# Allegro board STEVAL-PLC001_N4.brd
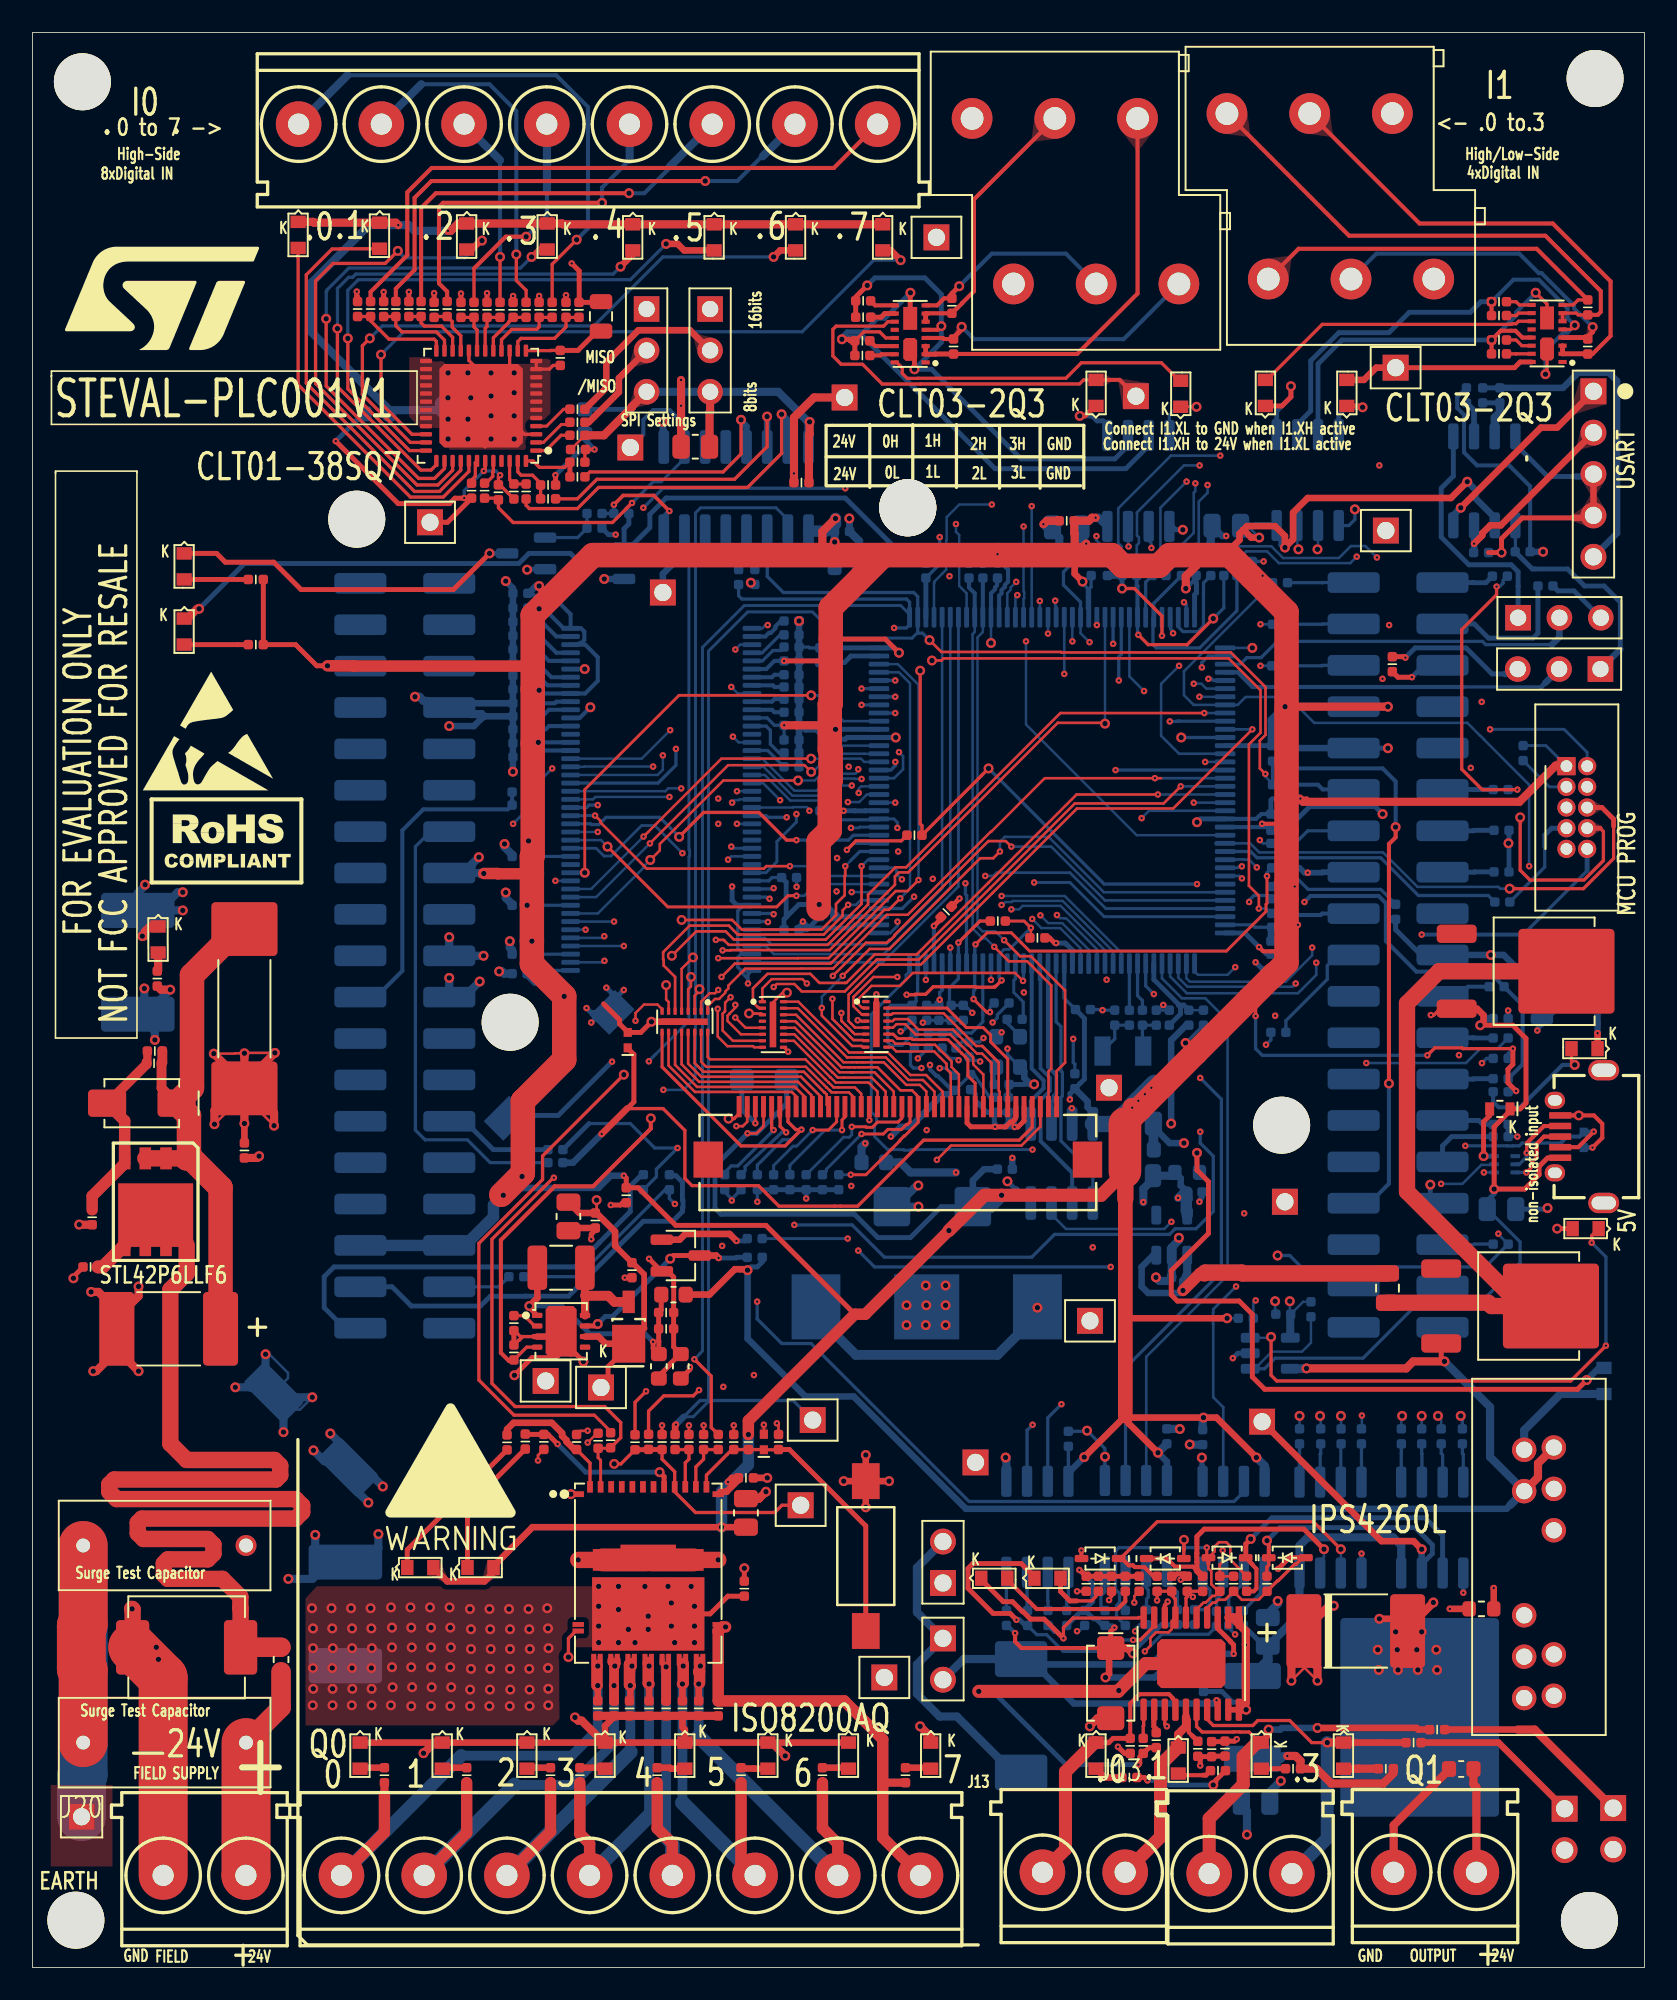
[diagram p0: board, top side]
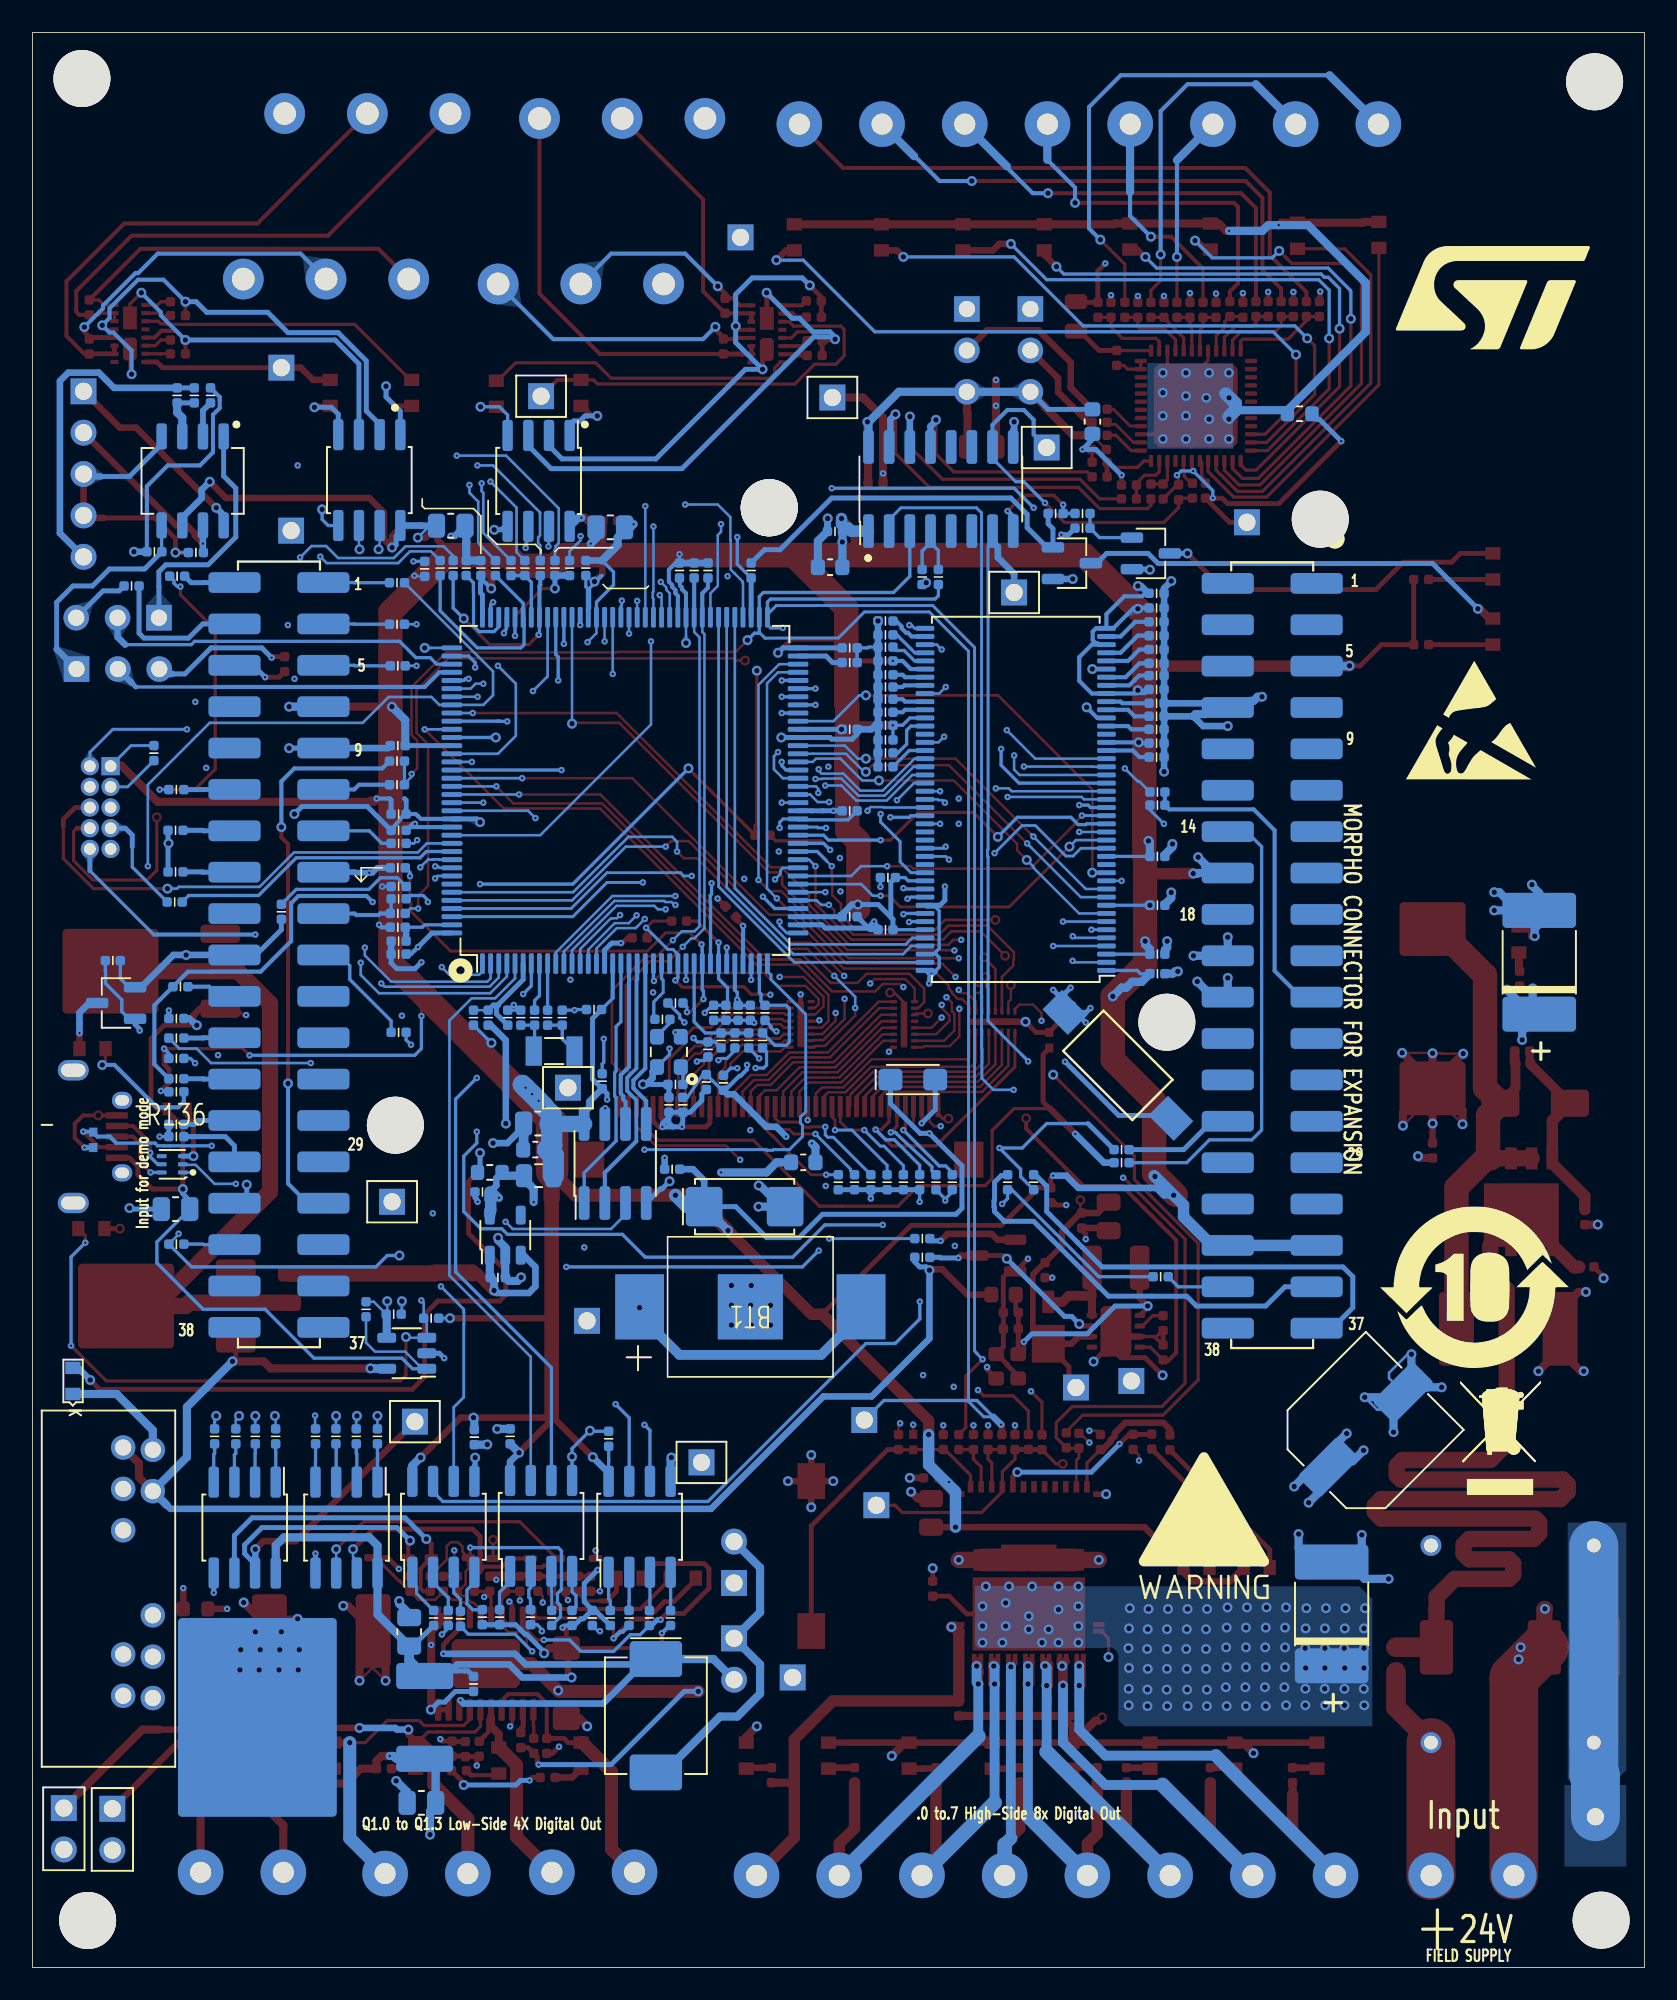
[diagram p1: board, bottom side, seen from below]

Outline 98.99 x 118.77 mm; copper layers: TOP, POWER PLANE, LOGIC_PLANE, BOTTOM. Coordinates in mm from the lower left corner of the outline.
Outline path: 0,118.77 0,0 98.99,0 98.99,118.77 0,118.77

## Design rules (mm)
constraint set DEFAULT: min track width 0.152, pair gap 0.15
net group FMC_ADD[0..13]: nets FMC_ADD.A0 FMC_ADD.A1 FMC_ADD.A2 FMC_ADD.A3 FMC_ADD.A4 FMC_ADD.A5 FMC_ADD.A6 FMC_ADD.A7 FMC_ADD.A8 FMC_ADD.A9 FMC_ADD.A10 FMC_ADD.A11 FMC_ADD.BA_0 FMC_ADD.BA_1
net group FMC_CTRL[0..7]: nets FMC_CTRL.NBL0 FMC_CTRL.NBL1 FMC_CTRL.SDCKE0 FMC_CTRL.SDCLK FMC_CTRL.SDNCAS FMC_CTRL.SDNE0 FMC_CTRL.SDNRAS FMC_CTRL.SDNWE
net group FMC_DATA[0..15]: nets FMC_DATA.D0 FMC_DATA.D1 FMC_DATA.D2 FMC_DATA.D3 FMC_DATA.D4 FMC_DATA.D5 FMC_DATA.D6 FMC_DATA.D7 FMC_DATA.D8 FMC_DATA.D9 FMC_DATA.D10 FMC_DATA.D11 FMC_DATA.D12 FMC_DATA.D13 FMC_DATA.D14 FMC_DATA.D15
net group LCD_BLUE[0..5]: nets LCD_BLUE.B2 LCD_BLUE.B3 LCD_BLUE.B4 LCD_BLUE.B5 LCD_BLUE.B6 LCD_BLUE.B7
net group LCD_GREEN[0..5]: nets LCD_GREEN.G2 LCD_GREEN.G3 LCD_GREEN.G4 LCD_GREEN.G5 LCD_GREEN.G6 LCD_GREEN.G7
net group LCD_RED[0..5]: nets LCD_RED.R2 LCD_RED.R3 LCD_RED.R4 LCD_RED.R5 LCD_RED.R6 LCD_RED.R7
net group USB[0..5]: nets USB.OTG_FS_DM USB.OTG_FS_DP USB.OTG_FS_ID USB.OTG_FS_VBUS USB.OVER_CURRENT USB.POWER_SWITCH_ON

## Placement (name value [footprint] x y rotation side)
BT1  3030TR  [CELL_HOLDER_KEYSTONE-3030TR]  54.91 40.55 0 bottom
C1  33pF  [C_0402]  28.61 90.55 90 top
C2  33pF  [C_0402]  29.56 90.6 270 top
C3  33pF  [C_0402]  31.66 91 0 top
C4  33pF  [C_0402]  33.46 92.4 0 top
C5  4.7uF  [C_0805]  40.7 93.35 180 top
C6  100nF  [C_0402]  33.5 93.18 180 top
C7  22nF  [C_0402]  31.11 101.75 270 top
C8  22nF  [C_0402]  29.51 101.75 270 top
C9  22nF  [C_0402]  27.91 101.75 270 top
C10  22nF  [C_0402]  26.31 101.75 270 top
C11  33nF  [C_0402]  32.41 98.8 270 top
C12  22nF  [C_0402]  24.66 101.75 270 top
C13  22nF  [C_0402]  23.11 101.8 270 top
C14  100nF  [C_0402]  47.22 91.15 180 top
C15  10uF  [C_0603]  50.01 85.95 0 bottom
C16  100nF  [C_0402]  49.71 88.15 0 bottom
C17  22nF  [C_0402]  21.56 101.8 270 top
C18  22nF  [C_0402]  19.96 101.8 270 top
C19  10nF  [C_0402]  51.01 101.3 180 top
C20  10nF  [C_0402]  56.46 102 90 top
C21  10nF  [C_0402]  50.96 98.95 180 top
C22  4.7uF  [C_0805]  63.51 88.4 180 bottom
C23  10nF  [C_0402]  56.56 99.5 90 top
C24  100nF  [C_0402]  63.51 88.8 0 top
C25  10nF  [C_0402]  90.06 101.4 180 top
C26  10nF  [C_0402]  95.51 101.9 90 top
C27  10nF  [C_0402]  90.06 99.05 180 top
C28  10nF  [C_0402]  95.51 99.5 90 top
C29  100nF  [C_0402]  74.91 85.85 270 bottom
C30  4.7uF  [C_0805]  73.31 88.5 180 bottom
C31  100nF  [C_0402]  66.26 23.55 90 top
C32  1pF  [C_0402]  72.91 23.55 270 top
C33  1pF  [C_0402]  73.76 23.55 270 top
C34  1uF  [C_0402]  72.41 13.4 90 top
C35  100nF  [C_0402]  67.96 23.55 90 top
C36  100n  [C_0402]  73.23 13.43 90 top
C37  4.7uF/63V  [TAN_2917]  81.26 20.65 0 top
C38  1pF  [C_0402]  70.91 23.55 270 top
C39  1pF  [C_0402]  69.96 23.55 270 top
C40  1uF  [C_0402]  64.71 23.55 270 top
C41  100nF  [C_0402]  71.86 32.55 270 bottom
C42  100nF  [C_0402]  69.66 32.6 90 bottom
C43  1uF  [C_0402]  64.61 21.45 270 bottom
C44  100nF  [C_0402]  63.61 32.45 90 bottom
C45  4.7uF/63V  [TAN_2917]  19.21 21.7 90 bottom
C46  10pF  [C_0402]  43.71 23.25 270 top
C47  22nF  [C_0402]  42.11 15.9 90 top
C48  22nF  [C_0402]  40.91 15.9 90 top
C49  22nF  [C_0402]  39.91 15.9 90 top
C50  10pF  [C_0402]  43.06 32.25 270 top
C51  22nF  [C_0402]  38.91 15.9 90 top
C52  22nF  [C_0402]  37.86 15.9 90 top
C53  33pF  [C_0402]  34.73 32.33 270 top
C54  33pF  [C_0402]  38.66 32.25 270 top
C55  33pF  [C_0402]  41.21 32.25 270 top
C56  22nF  [C_0402]  36.66 15.9 90 top
C57  33pF  [C_0402]  40.31 32.25 270 top
C58  22nF  [C_0402]  35.71 15.9 90 top
C59  22nF  [C_0402]  34.71 15.9 90 top
C60  4.7uF  [C_0805]  43.81 27.9 90 top
C61  100nF  [C_0402]  43.81 30.05 0 top
C62  10nF  [C_0402]  38.91 40.2 180 top
C63  4.7uF  [C_0805]  32.91 46.1 270 top
C64  10nF  [C_0402]  38.91 39.2 180.1 top
C65  4.7uF  [C_0603]  38.46 36.9 270 top
C66  10nF  [C_0402]  36.81 42.8 90 top
C67  100nF  [C_0402]  36.46 47.4 90 top
C68  4.7uF  [CAPPM320X160X120L75X120N]  44.93 54.5 180 bottom
C69  100nF  [C_0402]  29.91 61 180 bottom
C70  100nF  [C_0402]  29.91 62.2 180 bottom
C71  100nF  [C_0402]  46.61 63.7 0 bottom
C72  100nF  [C_0402]  29.91 65.2 180 bottom
C73  100nF  [C_0402]  46.46 66.9 0 bottom
C74  100nF  [C_0402]  29.91 68.2 180 bottom
C75  100nF  [C_0402]  29.96 75.15 180 bottom
C76  100nF  [C_0402]  46.61 75.35 0 bottom
C77  100nF  [C_0402]  46.61 76.25 0 bottom
C78  100nF  [C_0402]  29.96 78.45 180 bottom
C79  100nF  [C_0402]  46.61 80.2 0 bottom
C80  100nF  [C_0402]  29.96 84.35 180 bottom
C81  100nF  [C_0402]  29.96 83.45 180 bottom
C82  100nF  [C_0402]  64.01 54.4 270 bottom
C83  4.7uF  [C_0805]  67.96 51.8 0 bottom
C84  4n7/3kV  [CAPRB1000W60L1300T550H2000]  8.11 13.8 180 top
C85  4.7uF  [TAN_2917]  6.46 61.7 90 bottom
C86  2.2uF  [C_0402]  3.56 43 180 top
C87  4.7uF/63V  [TAN_2917]  8.36 39.2 180 top
C88  100uF  [CAPAE830X1000D890L290X95N]  17.11 33 135 bottom
C89  100nF  [C_0402]  13.01 50.15 270 top
C90  NM  [C_0402]  7.46 55.5 180 top
C91  4n7/3kV  [CAPRB1000W60L1300T550H2000]  8.11 25.9 0 top
C92  4.7uF  [C_0805]  90.21 46.55 0 bottom
C93  0.33  [C_0805]  75.11 10.1 0 bottom
C94  10nF  [C_0402]  71.91 17.4 90 bottom
C95  10uF  [C_0805]  75.86 20.6 90 bottom
C96  1uF  [C_0402]  71.36 47.6 0 bottom
C97  10nF  [C_0402]  59.71 49 0 bottom
C98  10uF  [C_0402]  70.41 42.35 180 bottom
C99  4.7uF  [C_0603]  68.11 50.2 0 bottom
C100  1pF/100V  [C_0402]  69.81 58.3 270 bottom
C101  2.2uF (Low ESR)  [C_0402]  72.36 85.9 270 bottom
C102  2.2uF (Low ESR)  [C_0402]  48.81 80.1 180 bottom
C103  1uF  [C_0402]  56.11 64.8 45 top
C104  1uF  [C_0402]  57.61 54.35 270 bottom
C105  100nF  [C_0402]  59.06 52.95 270 bottom
C106  1uF  [C_0402]  56.41 58.6 270 bottom
C107  100nF  [C_0402]  76.51 69.8 180 bottom
C108  100nF  [C_0402]  76.51 62.2 180 bottom
C109  100nF  [C_0402]  91.54 74.54 90 bottom
C110  220uF  [CAPPM600X320X280L130X220N]  55.26 46.7 180 bottom
C111  1uF  [C_0402]  54.91 58.6 270 bottom
C112  100nF  [C_0402]  55.66 58.6 90 bottom
C113  100nF  [C_0402]  76.51 70.8 0 bottom
C114  100nF  [C_0402]  64.51 58.8 180 bottom
C115  100nF  [C_0402]  57.16 58.6 90 bottom
C116  100nF  [C_0402]  48.81 64.5 0 bottom
C117  100nF  [C_0402]  48.81 71 0 bottom
C118  100nF  [C_0402]  48.81 76 0 bottom
C119  100nF  [C_0402]  48.81 81 0 bottom
C120  100nF  [C_0402]  59.26 85.75 90 bottom
C121  100nF  [C_0402]  65.01 85.9 270 bottom
C122  100nF  [C_0402]  71.46 85.9 270 bottom
C123  100nF  [C_0402]  76.56 75 180 bottom
C124  4.7pF_NPO_-+0.25pF_0402  [C_0402]  69.01 58.3 90 bottom
C125  4.7pF_NPO_-+0.25pF_0402  [C_0402]  66.46 58.3 90 bottom
C126  100nF  [C_0402]  59.91 52.95 270 bottom
C127  100nF  [C_0402]  61.71 63.2 180 top
C128  100nF  [C_0402]  34.56 45.85 90 top
C129  DNM  [C_0603]  33.9 94.89 270 bottom
C130  10nF  [C_0603]  87.74 12.18 180 top
D1  GREEN  [DIOC160X80X60L30]  16.31 106.35 90 top
D2  GREEN  [DIOC160X80X60L30]  21.31 106.3 90 top
D3  GREEN  [DIOC160X80X60L30]  26.66 106.25 90 top
D4  GREEN  [DIOC160X80X60L30]  31.61 106.25 90 top
D5  GREEN  [DIOC160X80X60L30]  36.86 106.2 90 top
D6  GREEN  [DIOC160X80X60L30]  41.86 106.2 90 top
D7  GREEN  [DIOC160X80X60L30]  46.86 106.2 90 top
D8  GREEN  [DIOC160X80X60L30]  52.21 106.2 90 top
D9  GREEN 2mA  [DIOC160X80X60L30]  65.31 96.65 270 top
D10  GREEN 2mA  [DIOC160X80X60L30]  70.51 96.6 270 top
D11  GREEN 2mA  [DIOC160X80X60L30]  75.71 96.65 270 top
D12  GREEN 2mA  [DIOC160X80X60L30]  80.71 96.65 270 top
D13  GREEN  [DIOC160X80X60L30]  80.51 13 90 top
D14  GREEN  [DIOC160X80X60L30]  75.46 13 90 top
D15  GREEN  [DIOC160X80X60L30]  70.36 12.7 90 top
D16  GREEN  [DIOC160X80X60L30]  65.31 13 90 top
D17  BAT20JFILM  [SODFL250X125X85L40X32N]  77.06 25.15 0 top
D18  BAT20JFILM  [SODFL250X125X85L40X32N]  73.36 25.15 180 top
D19  BAT20JFILM  [SODFL250X125X85L40X32N]  69.56 25.1 0 top
D20  BAT20JFILM  [SODFL250X125X85L40X32N]  65.56 25.1 180 top
D21  RED  [DIOC160X80X60L30]  59.06 23.89 180 top
D22  RED  [DIOC160X80X60L30]  62.33 23.89 180 top
D23  SMC30J22CA  [D_SMC]  60.71 15.45 270 bottom
D24  GREEN  [DIOC160X80X60L30]  55.16 13 90 top
D25  GREEN  [DIOC160X80X60L30]  50.11 13 90 top
D26  GREEN  [DIOC160X80X60L30]  45.16 13 90 top
D27  ESDALC6V1-1M2  [DIODFN2_100X60X50L25X50]  44.91 32.25 90 top
D28  GREEN  [DIOC160X80X60L30]  40.06 13 90 top
D29  RED  [DIOC160X80X60L30]  23.81 24.55 180 top
D30  GREEN  [DIOC160X80X60L30]  35.16 13 90 top
D31  GREEN  [DIOC160X80X60L30]  30.36 13 90 top
D32  GREEN  [DIOC160X80X60L30]  25.16 13 90 top
D33  GREEN  [DIOC160X80X60L30]  20.11 13 90 top
D34  GREEN  [DIOC160X80X60L30]  27.51 24.55 180 top
D35  STPS1L40M  [DO216-AA_STMITE]  36.61 39.3 90 top
D36  Blue (Debug LED)  [DIOC160X80X60L30]  9.31 82 90 top
D37  Amber (Debug LED)  [DIOC160X80X60L30]  9.31 86 90 top
D38  SMAJ15A-TR  [D_SMA]  6.71 53.05 180 top
D39  SM15T33CA  [D_SMC_BID]  9.46 19.65 0 top
D40  BLUE  [DIOC160X80X60L30]  7.71 63.1 90.1 top
D41  GREEN  [DIOC160X80X60L30]  95.38 45.35 0 top
D42  SMA6F5.0A  [SODFL517X257X110L97X145N]  66.21 17.45 270 top
D43  ESDA7P120-1U1M  [DIODFN2_160X100X60L35X80]  90.11 52.7 180 top
D44  ESDALC6V1-1M2  [DIODFN2_100X60X50L25X50]  95.26 50.8 270 bottom
D45  STPS5L25B-TR  [DPAK4P228_972X240L120X77T520]  90.71 40.6 270 top
D46  STPS5L25B-TR  [DPAK4P228_972X240L120X77T520]  91.66 61.15 270 top
D47  Amber  [DIOC160X80X60L30]  95.31 56.4 0 top
D48  GREEN  [DIOC160X80X60L30]  96.51 36 270 bottom
D49  ESDALC6V1-1M2  [DIODFN2_100X60X50L25X50]  36.55 56.92 90 top
F1  SF-0603HI700M-2 (7A FUSE)  [F_0603]  15.26 18.9 90 top
J1  CON8  [MOR8_5_08MM]  49.36 113.15 270 top
J2  3 pin jumper  [STRIP1X3_254]  37.71 101.8 180 top
J4  3 pin jumper  [STRIP1X3_254]  41.61 101.8 180 top
J6  CON6-2315  [MOR6_WURTH-691231510006]  67.86 113.5 180 top
J7  CON6-2315  [MOR6_WURTH-691231510006]  83.51 113.8 180 top
J8  2 pin jumper 2.54mm  [JUMPER_P254_2PIN]  94.09 9.74 270 bottom
J9  2 pin jumper 2.54mm  [JUMPER_P254_2PIN]  97.07 9.78 270 bottom
J10  2 pin jumper 2.54mm  [JUMPER_P254_2PIN]  55.91 23.6 90 top
J11  CON2  [MOR2_5_08MM]  74.8 5.76 90 top
J12  2 pin jumper 2.54mm  [JUMPER_P254_2PIN]  55.91 20.2 270 top
J13  CON2  [MOR2_5_08MM]  64.56 5.84 90 top
J14  CON8  [MOR8_5_08MM]  21.51 5.65 90 top
J17  con38-2x19-strip-male (MORPHO)  [CONN_MORPHO_SMD2X19X254]  22.86 62.1 270 bottom
J18  con38-2x19-strip-male (MORPHO)  [CONN_MORPHO_SMD2X19X254]  83.86 62.15 270 bottom
J19  CON2  [MOR2_5_08MM]  10.56 5.65 90 top
J20  Surge test Pad  [HDRV1W64P0_1X1_254X254H834]  3.01 9.25 0 top
J22  3 pin jumper  [STRIP1X3_254]  91.23 82.85 270 top
J23  CON10A  [SHDRV10W40P127_5X2_1265X510H-1]  94.2 73.74 270 top
J24  3 pin jumper  [STRIP1X3_254]  96.29 79.7 90 top
J25  con5-strip-male  [HDRV5W64P254_5X1_1270X254H838]  95.86 96.75 270 top
J26  CON2  [MOR2_5_08MM]  86.13 5.84 90 top
L1  600 Ohms  [C_0603]  39.36 41.3 180 top
L2  LQH32PN3R3NN0L  [BEAD_1210]  32.46 42.95 0 top
L3  600 Ohms  [C_0603]  39.81 36.9 90 top
L4  100Ohms  [BEADC850X300X250L90N]  13.01 58.85 270 top
L5  220 Ohms  [BEAD_0805]  67.91 48.6 180 bottom
L6  600 Ohms  [C_0603]  51.66 49.42 180 bottom
L7  220 Ohms  [BEAD_0805]  83.21 41.7 90 top
NOREF  -  []  -17.27 191.89 0 top
NOREF#2  -  []  26.71 24.55 0 top
NOREF#3  -  []  -17.27 191.89 0 top
NOREF#4  -  []  70.51 95.8 90 top
NOREF#5  -  []  60.71 51.35 0 top
NOREF#6  -  []  65.66 47.4 90 top
NOREF#7  -  []  16.31 105.55 90 top
NOREF#8  -  []  -15.09 39.2 0 top
NOREF#9  -  []  8.02 5.65 0 top
NOREF#10  -  []  26.71 24.55 0 top
NOREF#11  -  []  18.65 20.77 0 top
NOREF#12  -  []  96.51 35.2 90 top
NOREF#13  -  []  50.07 21.5 0 top
NOREF#14  -  []  46.86 105.4 90 top
NOREF#15  -  []  61.53 23.89 0 top
NOREF#16  -  []  30.36 12.2 90 top
NOREF#17  -  []  65.31 95.85 90 top
NOREF#18  -  []  -35.32 217.05 0 top
NOREF#19  -  []  31.61 105.45 90 top
NOREF#20  -  []  23.01 24.55 0 top
NOREF#21  -  []  41.86 105.4 90 top
NOREF#22  -  [unnamed#2]  53.75 89.7 0 top
NOREF#23  -  []  12.11 36.95 90 top
NOREF#24  -  []  -17.27 191.89 0 top
NOREF#25  -  []  5.9 60.77 0 top
NOREF#26  -  [unnamed#2]  76.71 51.8 0 top
NOREF#27  -  [unnamed#2]  29.33 58.12 0 top
NOREF#28  -  []  20.11 12.2 90 top
NOREF#29  -  []  6.77 70.47 0 top
NOREF#30  -  []  50.11 12.2 90 top
NOREF#31  -  []  20.13 84.96 0 top
NOREF#32  -  []  65.31 12.2 90 top
NOREF#33  -  []  96.51 35.2 90 top
NOREF#34  -  []  7.71 63.9 0 top
NOREF#35  -  []  55.16 12.2 90 top
NOREF#36  -  []  10.21 59.45 90 top
NOREF#37  -  []  70.51 95.8 90 top
NOREF#38  -  []  21.31 105.5 90 top
NOREF#39  -  []  23.01 24.55 0 top
NOREF#40  -  []  62.87 127.75 90 top
NOREF#41  -  []  41.86 105.4 90 top
NOREF#42  -  []  26.66 105.45 90 top
NOREF#43  -  []  81.13 85.01 0 top
NOREF#44  -  []  58.26 23.89 0 top
NOREF#45  -  []  5.66 49.66 0 top
NOREF#46  -  [unnamed#2]  53.75 89.7 0 top
NOREF#47  -  []  0.95 96.96 0 top
NOREF#48  -  []  36.86 105.4 90 top
NOREF#49  -  []  75.71 95.85 90 top
NOREF#50  -  []  93.44 47.25 90 top
NOREF#51  -  [unnamed#2]  3.06 115.85 0 top
NOREF#52  -  []  5.88 16.52 0 top
NOREF#53  -  []  40.06 12.2 90 top
NOREF#54  -  []  85.01 18.4 90 top
NOREF#55  -  []  83.59 5.84 0 top
NOREF#56  -  []  94.51 56.4 0 top
NOREF#57  -  []  94.58 45.35 0 top
NOREF#58  -  []  58.26 23.89 0 top
NOREF#59  -  []  65.31 95.85 90 top
NOREF#60  -  []  9.31 85.2 90 top
NOREF#61  -  []  10.98 41.45 0 top
NOREF#62  -  []  10.06 56 0 top
NOREF#63  -  []  25.16 12.2 90 top
NOREF#64  -  []  91.23 82.85 0 top
NOREF#65  -  []  30.36 12.2 90 top
NOREF#66  -  []  93.49 48.77 90 top
NOREF#67  -  []  80.71 95.85 90 top
NOREF#68  -  []  6.15 19.65 0 top
NOREF#69  -  []  21.66 27.6 0 top
NOREF#70  -  [unnamed#2]  19.91 89 0 top
NOREF#71  -  []  55.16 12.2 90 top
NOREF#72  -  []  93.75 79.7 0 top
NOREF#73  -  []  13.04 16.52 90 top
NOREF#74  -  []  26.66 105.45 90 top
NOREF#75  -  []  45.16 12.2 90 top
NOREF#76  -  []  20.13 82.42 90 top
NOREF#77  -  []  61.53 23.89 0 top
NOREF#78  -  []  94.51 56.4 0 top
NOREF#79  -  []  21.31 105.5 90 top
NOREF#80  -  []  36.69 57.78 90 top
NOREF#81  -  []  9.31 85.2 90 top
NOREF#82  -  []  31.61 105.45 90 top
NOREF#83  -  []  70.36 11.9 90 top
NOREF#84  -  []  20.11 12.2 90 top
NOREF#85  -  []  94.58 45.35 0 top
NOREF#86  -  []  7.71 63.9 0 top
NOREF#87  -  []  96.49 46.92 90 top
NOREF#88  -  []  50.11 12.2 90 top
NOREF#89  -  []  80.51 12.2 90 top
NOREF#90  -  [unnamed#2]  2.66 3 0 top
NOREF#91  -  []  -17.27 191.89 0 top
NOREF#92  -  []  63.84 46.93 0 top
NOREF#93  -  []  70.36 11.9 90 top
NOREF#94  -  []  30.18 52.97 0 top
NOREF#95  -  []  65.31 12.2 90 top
NOREF#96  -  []  34.49 57.78 0 top
NOREF#97  -  []  80.71 95.85 90 top
NOREF#98  -  []  52.27 19.8 90 top
NOREF#99  -  []  77.51 22.9 0 top
NOREF#100  -  []  75.46 12.2 90 top
NOREF#101  -  []  52.21 105.4 90 top
NOREF#102  -  []  35.16 12.2 90 top
NOREF#103  -  []  35.16 12.2 90 top
NOREF#104  -  []  41.61 99.26 90 top
NOREF#105  -  []  72.26 5.76 0 top
NOREF#106  -  []  37.71 99.26 90 top
NOREF#107  -  []  22.96 19.45 90 top
NOREF#108  -  []  25.16 12.2 90 top
NOREF#109  -  []  36.86 105.4 90 top
NOREF#110  -  []  75.46 12.2 90 top
NOREF#111  -  []  52.21 105.4 90 top
NOREF#112  -  []  7.31 65.2 0 top
NOREF#113  -  []  81.13 82.47 90 top
NOREF#114  -  []  93.82 49.7 90 top
NOREF#115  -  []  16.31 105.55 90 top
NOREF#116  -  [unnamed#2]  95.61 2.98 0 top
NOREF#117  -  []  40.06 12.2 90 top
NOREF#118  -  []  80.51 12.2 90 top
NOREF#119  -  []  50.07 19.8 0 top
NOREF#120  -  []  46.86 105.4 90 top
NOREF#121  -  []  15.06 50 90 top
NOREF#122  -  []  9.31 81.2 90 top
NOREF#123  -  []  45.16 12.2 90 top
NOREF#124  -  [unnamed#2]  95.96 116.05 0 top
NOREF#125  -  []  9.31 81.2 90 top
NOREF#126  -  []  62.02 5.84 0 top
NOREF#127  -  []  75.71 95.85 90 top
NOREF#128  -  []  93.44 47.25 0 top
NOREF#129  -  []  14.65 71.14 180 bottom
NOREF#130  -  []  16.31 97 180 bottom
NOREF#131  -  []  31.06 24.6 180 bottom
NOREF#132  -  []  16.23 36.78 180 bottom
NOREF#133  -  []  11.31 29 180 bottom
Q1  2STR1160  [SOT23-3P97_255X140L40X40N]  39.81 43.7 270 top
Q2  2STR1160  [SOT23-3P97_255X140L40X40N]  35.16 86.2 270 bottom
Q3  2STR1160  [SOT23-3P97_255X140L40X40N]  30.31 86.8 270 bottom
Q4  STL42P6LLF6  [POWER_FLAT_5X6]  7.56 47 180 top
Q5  2STR1160  [SOT23-3P97_255X140L40X40N]  93.86 59.2 90 bottom
R1  220R  [R_0402]  33.46 91.5 0 top
R2  220R  [R_0402]  31.66 90.15 0 top
R3  220R  [R_0402]  30.31 90.6 270 top
R4  220R  [R_0402]  27.76 90.65 270 top
R5  15K  [R_0402]  26.96 90.65 270 top
R6  0E  [R_0402]  33.46 94.05 0 top
R7  2K2  [R_0402]  31.91 101.75 270 top
R8  1K  [R_0402]  33.46 94.85 0 top
R9  2K2  [R_0402]  30.31 101.75 270 top
R10  1K  [R_0402]  33.46 95.65 0 top
R11  2K2  [R_0402]  28.71 101.75 270 top
R12  2K2  [R_0402]  27.11 101.75 270 top
R13  1K  [R_0805]  34.91 101.35 270 top
R14  2K2  [R_0402]  25.46 101.8 270 top
R15  1M5  [R_0402]  33.56 101.75 270 top
R16  120K  [R_0402]  32.76 101.75 90 top
R17  2K2  [R_0402]  23.86 101.8 270 top
R18  120E  [R_0402]  43.36 85.35 90 bottom
R19  2K2  [R_0402]  22.31 101.8 270 top
R20  120E  [R_0402]  44.36 85.35 90 bottom
R21  120E  [R_0402]  59.51 59.2 0 bottom
R22  2K2  [R_0402]  20.76 101.8 270 top
R23  0E  [R_0402]  51.01 102.3 0 top
R24  0E  [R_0402]  50.96 99.85 0 top
R25  0E  [R_0402]  90.06 102.25 0 top
R26  0E  [R_0402]  90.06 99.9 0 top
R27  7.5K  [R_0402]  83.11 12.2 180 top
R28  7.5K  [R_0402]  77.41 12.2 180 top
R29  7.5K  [R_0402]  72.8 12.08 180 top
R30  7.5K  [R_0402]  67.36 11.66 180 top
R31  330R  [R_0402]  85.31 32.6 90 bottom
R32  510R  [R_0402]  84.06 32.6 90 bottom
R33  5.1K  [R_0402]  75.81 23.55 90 top
R34  330R  [R_0402]  86.51 32.6 90 bottom
R35  5.1K  [R_0402]  74.56 23.55 270 top
R36  510R  [R_0402]  87.81 32.6 90 bottom
R37  52K  [R_0402]  84.81 13.8 0 top
R38  52K  [R_0402]  86.26 14.6 0 top
R39  330R  [R_0402]  79.11 32.6 90 bottom
R40  52K  [R_0402]  67.41 13.6 270 top
R41  5.1K  [R_0402]  71.86 23.55 90 top
R42  330R  [R_0402]  80.36 32.6 90 bottom
R43  5.1K  [R_0402]  69.06 23.55 90 top
R44  220K  [R_0402]  68.21 13.6 270 top
R45  52K  [R_0402]  71.56 13.42 270 top
R46  510R  [R_0402]  77.81 32.6 90 bottom
R47  60.4K  [R_0402]  69.01 13.95 270 top
R48  510R  [R_0402]  81.61 32.6 90 bottom
R49  620R  [R_0402]  71.36 21.5 270 bottom
R50  200R  [R_0402]  72.71 21.4 270 bottom
R51  2.5K  [R_0402]  67.11 23.55 90 top
R52  1K  [R_0402]  65.46 23.55 90 top
R53  200R  [R_0402]  73.46 21.45 270 bottom
R54  620R  [R_0402]  74.36 21.45 270 bottom
R55  620R  [R_0402]  65.86 21.45 270 bottom
R56  200R  [R_0402]  67.11 21.45 270 bottom
R57  200R  [R_0402]  68.41 21.5 270 bottom
R58  620R  [R_0402]  70.31 21.5 270 bottom
R59  620R  [R_0402]  59.81 21.45 270 bottom
R60  200R  [R_0402]  61.11 21.45 270 bottom
R61  200R  [R_0402]  62.36 21.45 270 bottom
R62  620R  [R_0402]  63.51 21.45 270 bottom
R63  7.5K  [R_0402]  53.61 11.8 90 top
R64  1K  [R_0402]  45.81 32.25 90 top
R65  10K  [R_0402]  43.96 32.25 90 top
R66  7.5K  [R_0402]  48.51 11.8 90 top
R67  7.5K  [R_0402]  43.51 11.8 90 top
R68  220E  [R_0402]  42.11 32.25 270 top
R69  220E  [R_0402]  39.46 32.25 270 top
R70  7.5K  [R_0402]  38.36 11.8 90 top
R71  220E  [R_0402]  37 32.24 270 top
R72  NM  [R_0402]  37.83 32.26 270 top
R73  7.5K  [R_0402]  33.61 11.8 90 top
R74  100E  [R_0402]  35.5 32.36 270 top
R75  100E  [R_0402]  57.51 56.35 270 bottom
R76  750E  [R_0402]  29.14 32.23 90 top
R77  7.5K  [R_0402]  31.81 11.8 90 top
R78  220E  [R_0402]  33.41 32.25 90 top
R79  7.5K  [R_0402]  26.66 11.8 90 top
R80  7.5K  [R_0402]  21.61 11.8 90 top
R81  750E  [R_0402]  30.26 32.28 90 top
R82  220E  [R_0402]  31.4 32.26 90 top
R83  4K7  [R_0402]  44.35 43.59 180 bottom
R84  22K  [R_0402]  44.35 44.74 180 bottom
R85  100K  [R_0402]  29.56 39.55 90 top
R86  10_1%  [R_0402]  29.56 37.75 270 top
R87  4K7  [R_0402]  42.51 48.2 270 bottom
R88  4K7  [R_0402]  43.51 48.2 90 bottom
R89  4K7  [R_0402]  45.51 48.2 270 bottom
R90  4K7  [R_0402]  46.51 48.2 90 bottom
R91  4K7  [R_0402]  47.51 48.2 270 bottom
R92  4K7  [R_0402]  48.51 48.2 90 bottom
R93  4K7  [R_0402]  44.51 48.2 270 bottom
R94  330E  [R_0402]  13.71 81.2 180 top
R95  NM  [R_0402]  29.91 72.15 0 bottom
R96  NM  [R_0402]  29.91 71.35 0 bottom
R97  47k  [R_0402]  54.86 85.75 90 bottom
R98  NM  [R_0402]  39.11 48.2 270 bottom
R99  NM  [R_0402]  37.51 48.2 270 bottom
R100  10K_1  [R_0402]  29.96 74.3 0 bottom
R101  10K_1  [R_0402]  46.61 73.7 0 bottom
R102  22K  [R_0402]  36.16 89.25 180 bottom
R103  10K_1  [R_0402]  46.61 74.55 0 bottom
R104  NM  [R_0402]  76.61 85 180 bottom
R105  NM  [R_0402]  76.61 82.45 180 bottom
R106  NM  [R_0402]  92.91 84.8 180 bottom
R107  10K_1  [R_0402]  29.96 76.8 0 bottom
R108  NM  [R_0402]  76.56 79.9 180 bottom
R109  NM  [R_0402]  83.51 80 270 top
R110  10K_1  [R_0402]  29.96 77.6 0 bottom
R111  10K_1  [R_0402]  46.61 77.85 0 bottom
R112  10K_1  [R_0402]  29.96 79.3 0 bottom
R113  NM  [R_0402]  76.61 72.6 180 bottom
R114  10K_1  [R_0402]  29.96 76 0 bottom
R115  NM  [R_0402]  90.11 85.4 180 bottom
R116  10K_1  [R_0402]  46.61 77.05 0 bottom
R117  10K_1  [R_0402]  46.61 78.6 0 bottom
R118  NM  [R_0402]  90.16 72.3 180 bottom
R119  10K_1  [R_0402]  29.96 80.05 0 bottom
R120  10K_1  [R_0402]  46.61 79.35 0 bottom
R121  NM  [R_0402]  76.51 69 180 bottom
R122  NM  [R_0402]  90.21 69.8 180 bottom
R123  NM  [R_0402]  90.21 67.25 180 bottom
R124  10K_1  [R_0402]  29.96 80.9 0 bottom
R125  10K_1  [R_0402]  46.61 81.05 0 bottom
R126  NM  [R_0402]  76.56 67.5 180 bottom
R127  10K_1  [R_0402]  29.96 81.75 0 bottom
R128  10K_1  [R_0402]  46.61 81.8 0 bottom
R129  NM  [R_0402]  76.56 64.7 180 bottom
R130  120  [R_0402]  76.51 65.6 180 bottom
R131  NM  [R_0402]  89.91 60.2 180 bottom
R132  10K_1  [R_0402]  29.96 82.6 0 bottom
R133  10K_1  [R_0402]  46.61 82.65 0 bottom
R134  NM  [R_0402]  90.16 57.05 180 bottom
R135  NM  [R_0402]  90.16 54.55 180 bottom
R136  NM  [R_0402]  90.16 51.75 180 bottom
R137  330E  [R_0402]  13.71 85.2 180 top
R138  NM  [R_0402]  90.16 51 180 bottom
R139  NM  [R_0402]  90.16 44.4 180 bottom
R140  47k  [R_0402]  34.51 88.35 180 bottom
R141  22K  [R_0402]  34.51 89.25 0 bottom
R142  7.2k  [R_0402]  7.66 60.7 270 top
R143  1K  [R_0402]  90.16 55.8 0 bottom
R144  470K  [R_0402]  7.51 56.25 180 top
R145  330K  [R_0402]  3.66 46.05 90 top
R146  47k  [R_0402]  74.51 39.85 0 bottom
R147  10K  [R_0402]  76.81 40.1 0 bottom
R148  47k  [R_0402]  90.16 58.25 0 bottom
R149  330E  [R_0402]  90.16 53.75 180 bottom
R150  470E  [R_0603]  70.91 48.8 0 bottom
R151  22K  [R_0402]  94.06 61.8 180 bottom
R152  0E  [R_0402]  54.01 58.6 270 bottom
R153  0E  [R_0402]  54.16 56.9 270 bottom
R154  0  [R_0402]  55.86 56.9 270 bottom
R155  120  [R_0402]  56.71 56.9 270 bottom
R156  0  [R_0402]  55.01 56.9 270 bottom
R157  0E  [R_0402]  73.16 85.9 90 bottom
R158  NM  [R_0402]  67.81 85.9 90 bottom
R159  NM  [R_0402]  69.61 85.9 90 bottom
R160  0E  [R_0402]  68.76 85.9 90 bottom
R161  0E  [R_0402]  70.56 85.9 90 bottom
R162  NM  [R_0402]  73.96 85.9 90 bottom
R163  0E  [R_0402]  66.91 85.9 90 bottom
R164  NM  [R_0402]  66.01 85.9 90 bottom
R165  100  [R_0402]  54.16 69.5 0 top
R167  2K7  [R_0402]  57.51 85.75 270 bottom
R168  0  [R_0402]  56.56 54.3 270 bottom
R169  2K7  [R_0402]  58.36 85.75 270 bottom
R170  10K  [R_0402]  76.51 66.35 180 bottom
R171  10K  [R_0402]  83.71 64.8 270 bottom
R172  0  [R_0402]  88.06 96.5 270 bottom
R173  0  [R_0402]  68.16 58.3 90 bottom
R174  0  [R_0402]  89.06 96.5 270 bottom
R175  0  [R_0402]  90.11 96.5 270 bottom
R176  0  [R_0402]  91.51 86.9 180 bottom
R177  0  [R_0402]  88.96 86.85 180 bottom
R178  100_1%  [R_0402]  60.31 58.2 0 bottom
R179  10K  [R_0402]  76.56 63.85 180 bottom
R180  0  [R_0402]  67.36 58.3 90 bottom
R181  10K  [R_0402]  76.51 63 0 bottom
R182  10K  [R_0402]  59.28 64.23 180 top
R183  10K  [R_0402]  59.51 54.2 180 bottom
R184  0  [R_0402]  71.01 58.3 270 bottom
R185  0  [R_0402]  71.91 58.3 270 bottom
R186  NM  [R_0402]  32.11 49.4 180 bottom
R187  NM  [R_0402]  32.11 50.2 180 bottom
R188  NM  [R_0402]  29.71 42.4 180 bottom
R189  NM  [R_0402]  76.51 57.4 180 bottom
R190  NM  [R_0402]  76.61 74.05 180 bottom
R191  0  [R_0402]  90.26 65.4 0 bottom
R192  NM  [R_0402]  78.51 40.4 90 bottom
R193  4K7  [R_0402]  49.51 48.2 270 bottom
R194  0.0  [R_0603]  21.17 95.37 0 bottom
R195  0.0  [R_0603]  88.98 22.01 0 top
SW1  1437566-3  [PUSH_BUTTON_TECONN_1437566-3]  48.87 25.25 270 top
SW2  1437566-3  [PUSH_BUTTON_TECONN_1437566-3]  30.71 57 45 bottom
TP1  con1-strip-female  [RHDRV1W64P0_1X1_305X254H851]  36.71 93.3 180 bottom
TP2  con1-strip-female  [RHDRV1W64P0_1X1_305X254H851]  38.71 84.4 180 bottom
TP3  con1-strip-female  [RHDRV1W64P0_1X1_305X254H851]  64.94 39.69 0 top
TP4  con1-strip-female  [RHDRV1W64P0_1X1_305X254H851]  49.87 96.37 180 bottom
TP5  con1-strip-female  [RHDRV1W64P0_1X1_305X254H851]  67.76 96.45 180 bottom
TP6  con1-strip-female  [RHDRV1W64P0_1X1_305X254H851]  83.71 98.2 0 top
TP7  con1-strip-female  [RHDRV1W64P0_1X1_305X254H851]  75.51 33.5 180 bottom
TP8  con1-strip-female  [RHDRV1W64P0_1X1_305X254H851]  57.91 31 180 bottom
TP9  con1-strip-female  [RHDRV1W64P0_1X1_305X254H851]  47.91 33.6 0 top
TP10  con1-strip-female  [RHDRV1W64P0_1X1_305X254H851]  47.17 28.37 0 top
TP11  con1-strip-female  [RHDRV1W64P0_1X1_305X254H851]  34.91 35.6 0 top
TP12  con1-strip-female  [RHDRV1W64P0_1X1_305X254H851]  83.11 88.2 0 top
TP13  con1-strip-female  [RHDRV1W64P0_1X1_305X254H851]  52.31 17.8 0 top
TP14  con1-strip-female  [RHDRV1W64P0_1X1_305X254H851]  24.41 88.71 0 top
TP15  con1-strip-female  [RHDRV1W64P0_1X1_305X254H851]  76.91 47 180 bottom
TP16  con1-strip-female  [RHDRV1W64P0_1X1_305X254H851]  66.11 54 180 bottom
TP17  con1-strip-female  [RHDRV1W64P0_1X1_305X254H851]  55.51 106.2 0 top
TP18  con1-strip-female  [RHDRV1W64P0_1X1_305X254H851]  31.51 36 0 top
U1  CLT01-38SQ7-TR  [QFN49P50_700X700X100L40X25T513N]  27.55 95.86 90 top
U2  SI8661BD-B-IS  [SOIC16P127_990X600X175L83X41N]  43.21 90.75 180 bottom
U3  ACPL-024L-000E  [SOIC8P127_508X599X330L78X40]  67.91 91.25 0 bottom
U4  -  [CLT03-2Q3]  53.9 100.27 90 top
U5  -  [CLT03-2Q3]  93.01 100.3 90 top
U6  ACPL-024L-000E  [SOIC8P127_508X599X330L78X40]  78.31 91.3 0 bottom
U7  ACPL-024L-000E  [SOIC8P127_508X599X330L78X40]  85.96 27 0 bottom
U8  IPS4260L  [SOP21P65_650X640X120L60X24T420X300N]  71.16 18.65 180 top
U9  ACPL-024L-000E  [SOIC8P127_508X599X330L78X40]  79.71 27 0 bottom
U10  ACPL-024L-000E  [SOIC8P127_508X599X330L78X40]  73.76 27.05 180 bottom
U11  ACPL-024L-000E  [SOIC8P127_508X599X330L78X40]  67.76 27.1 180 bottom
U12  ACPL-024L-000E  [SOIC8P127_508X599X330L78X40]  61.71 27.05 180 bottom
U13  ISO8200AQ  [ST_TFQFPN32]  37.81 24.2 270 top
U14  STLD40DPUR  [SON9P65_300X300X100L40X30T310X190]  32.46 39.05 270 top
U15  FH12S-40S-05SH55  [CONN40_1X40_DRC_FFC]  53.14 49.41 180 top
U16  EMIF08-LCD04M16  [SON17P40_330X135X55L25X20T280X40]  51.82 57.89 270 top
U17  EMIF08-LCD04M16  [SON17P40_330X135X55L25X20T280X40]  45.47 57.88 270 top
U18  EMIF08-LCD04M16  [SON17P40_330X135X55L25X20T280X40]  40.06 58.05 180 top
U19  IS42S32400F-7TLI-TR  [SOP86P50_2222X1176X120L50X22N]  38.61 71.7 90 bottom
U20  W25X10CLSNIG  [SOIC8P127_490X600X175L83X42N]  63.21 49.35 180 bottom
U21  STMPS2151STR  [SOT23-5P95_280X145L45X40N]  76.01 37.7 90 bottom
U22  USB_micro_AB  [MICRO-USB_AB-MOLEX-0475900001]  96.49 51 180 top
U23  LM7805-d2pak  [DPAK4P254_1542X460L254X81T76-1]  81.61 15.35 90 bottom
U24  NCS1S2405SC  [NCS1]  92.51 25.2 90 top
U25  ECMF02_2AMX6  [SON6P50_170X150X55L40X24]  90.41 49.3 90 bottom
U26  LDK220M33R  [SOT23-5P95_280X145L45X40N]  69.96 44.95 180 bottom
U27  STM32F746ZGT7  [QFP144P50_2200X2200X160L60X22N]  62.61 72.25 180 bottom
U28  ILD207T  [SOIC8P127_599X610X350L51X41N]  89.16 91.25 0 bottom
U29  NCS1S2405SC  [NCS1]  94.33 23.25 270 bottom
Y1  NX3215SA-32.768K  [XTALDFN2_320X150X90L75X130]  66.96 56.25 0 bottom
Y2  ECS-2520MV-250-BN-TR  [OSCCC250X200X90L67X77N]  59.91 56.2 90 bottom

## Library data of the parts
BT1 = COIN_CELL_HOLDER_3PIN
C1-C4 C6-C14 C16-C21 C23-C29 C31-C36 C38-C44 C46-C59 C61 C62 C64 C66 C67 C69-C82 C86 C89 C90 C94 C96-C98 C100-C109 C111-C128 = CAP: alternate symbols: (c_0402_hd)
C5 C22 C30 C60 C63 C83 C92 C93 C95 = CAP: alternate symbols: (C_0805_hd)
C15 C65 C99 C129 = CAP: alternate symbols: (c_0603_hd)
C37 C45 C68 C85 C87 C88 C110 = CAP_P
C84 C91 C130 = CAP
D1-D16 D21 D22 D24-D26 D28-D34 D36 D37 D40 D41 D47 D48 = DIODE_LED
D17-D20 D35 = DIODE_SCHOTTKY
D23 = DIODE_SCHOTTKY_0
D27 D44 D49 = DIODE_TRANSIL: alternate symbols: (diodfn2_100x60x50l25x50l)
D38 D42 = DIODE_TRANSIL
D39 = DIODE_TRANSIL_BID
D43 = DIODE: alternate symbols: (diodfn2_160x100x60l35x80n)
D45 D46 = DIODE_SCHOTTKY_DPAK
F1 = FUSE
J1 J14 = CON8
J2 J4 J22 J24 = CON3AP
J6 J7 = CON6
J8-J10 J12 = JUMPER
J11 J13 J19 J26 = CON2
J17 J18 = CON38A
J20 TP1-TP18 = CON1
J23 = CON10A
J25 = CON5
L1-L7 = IND_FB
Q1-Q3 Q5 = BJT_NPN_BEC
Q4 = MOSFET_P_DIODE_SSSGDDDD
R1-R12 R14-R149 R151-R165 R167-R193 = RES: alternate symbols: (r_0402_hd)
R13 R150 R194 R195 = RES
SW1 SW2 = PUSHBUTTON
U1 = CLT01_38SQ7_TR
U2 = Si8661_1
U3 U6 U7 U9 = ACPL-024L
U4 U5 = CLT03-2Q3
U8 = IPS4260L
U10 = ACPL-024L_5
U11 = ACPL-024L_4
U12 = ACPL-024L_3
U13 = ISO8200AQ_9
U14 = STLD40DPUR_0
U15 = FH12S-40S-05SH55
U16-U18 = EMIF08-LCD04M16
U19 = IS42S32400F_TSOP
U20 = W25X10CLSNIG
U21 = STMPS2151STR
U22 = USB_micro_2
U23 = L78xx-143
U24 U29 = NCS1
U25 = ECMF02_2AMX6
U26 = LDK220_0: alternate symbols: (sot23-5p95_280x145l45x40l)
U27 = STM32F74XZXT
U28 = ILD2xxx_0
Y1 = CRYSTAL
Y2 = CRYSTAL_4PIN

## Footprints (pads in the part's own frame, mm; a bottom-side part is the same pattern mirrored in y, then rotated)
BEAD_0805
  rrect 1x1.42 smd: 1(-0.9,0) 2(0.9,0)
BEAD_1210
  rrect 1.2x2.72 smd: 1(-1.46,0) 2(1.46,0)
BEADC850X300X250L90N
  rrect 3.3x4.06 smd: 1(-4.89,0) 2(4.89,0)
C_0402
  rrect 0.58x0.58 smd: 1(-0.46,0) 2(0.46,0)
C_0603
  rrect 0.87x0.97 smd: 1(-0.75,0) 2(0.75,0)
C_0805
  rrect 1.06x1.47 smd: 1(-0.875,0) 2(0.875,0)
CAPAE830X1000D890L290X95N
  rrect 3.51x1.92 smd: 1(-3.25,0) 2(3.25,0)
CAPPM320X160X120L75X120N
  rrect 1.46x1.33 smd: 1(-1.375,0) 2(1.375,0)
CAPPM600X320X280L130X220N
  rrect 2.25x2.42 smd: 1(-2.485,0) 2(2.485,0)
CAPRB1000W60L1300T550H2000
  round 1.28 hole 0.85: 1(-5,0) 2(5,0)
CELL_HOLDER_KEYSTONE-3030TR
  rect 3x4 smd: 1(-6.8,0) 2(6.8,0)
  rect 4x4 smd: 3(0,0)
CLT03-2Q3
  rect 0.25x0.5 smd: 1(-1.75,-0.95) 2(-1.25,-0.95) 3(-0.75,-0.95) 4(-0.25,-0.95) 5(0.25,-0.95) 6(0.75,-0.95) 7(1.25,-0.95) 8(1.75,-0.95) 9(1.75,0.95) 10(1.25,0.95) 11(0.75,0.95) 12(0.25,0.95) 13(-0.25,0.95) 14(-0.75,0.95) 15(-1.25,0.95) 16(-1.75,0.95)
  rrect 1.405x0.85 smd: TAB1(-0.953,0)
  rect 1.405x0.85 smd: TAB2(0.953,0)
CONN40_1X40_DRC_FFC
  rect 0.3x1.3 smd: 1(9.75,-3.429) 2(9.25,-3.429) 3(8.75,-3.429) 4(8.25,-3.429) 5(7.75,-3.429) 6(7.25,-3.429) 7(6.75,-3.429) 8(6.25,-3.429) 9(5.75,-3.429) 10(5.25,-3.429) 11(4.75,-3.429) 12(4.25,-3.429) 13(3.75,-3.429) 14(3.25,-3.429) 15(2.75,-3.429) 16(2.25,-3.429) 17(1.75,-3.429) 18(1.25,-3.429) 19(0.75,-3.429) 20(0.25,-3.429) 21(-0.25,-3.429) 22(-0.75,-3.429) 23(-1.25,-3.429) 24(-1.75,-3.429) 25(-2.25,-3.429) 26(-2.75,-3.429) 27(-3.25,-3.429) 28(-3.75,-3.429) 29(-4.25,-3.429) 30(-4.75,-3.429) 31(-5.25,-3.429) 32(-5.75,-3.429) 33(-6.25,-3.429) 34(-6.75,-3.429) 35(-7.25,-3.429) 36(-7.75,-3.429) 37(-8.25,-3.429) 38(-8.75,-3.429) 39(-9.25,-3.429) 40(-9.75,-3.429)
  rect 1.803x2.21 smd: 41(-11.646,-0.178) 42(11.646,-0.178)
CONN_MORPHO_SMD2X19X254
  rrect 1.27x3.2 smd: 1(-22.86,2.73) 2(-22.86,-2.73) 3(-20.32,2.73) 4(-20.32,-2.73) 5(-17.78,2.73) 6(-17.78,-2.73) 7(-15.24,2.73) 8(-15.24,-2.73) 9(-12.7,2.73) 10(-12.7,-2.73) 11(-10.16,2.73) 12(-10.16,-2.73) 13(-7.62,2.73) 14(-7.62,-2.73) 15(-5.08,2.73) 16(-5.08,-2.73) 17(-2.54,2.73) 18(-2.54,-2.73) 19(0,2.73) 20(0,-2.73) 21(2.54,2.73) 22(2.54,-2.73) 23(5.08,2.73) 24(5.08,-2.73) 25(7.62,2.73) 26(7.62,-2.73) 27(10.16,2.73) 28(10.16,-2.73) 29(12.7,2.73) 30(12.7,-2.73) 31(15.24,2.73) 32(15.24,-2.73) 33(17.78,2.73) 34(17.78,-2.73) 35(20.32,2.73) 36(20.32,-2.73) 37(22.86,2.73) 38(22.86,-2.73)
D_SMA
  rrect 2.34x1.67 smd: A(2.135,0) C(-2.135,0)
D_SMC
  rrect 2.2x3.22 smd: A(3.48,0) C(-3.48,0)
D_SMC_BID
  rrect 2.04x3.34 smd: 1(3.315,0) 2(-3.315,0)
DIOC160X80X60L30
  rect 0.76x0.93 smd: A(-0.8,0) C(0.8,0)
DIODFN2_100X60X50L25X50
  rect 0.55x0.5 smd: A(0.475,0) C(-0.475,0)
DIODFN2_160X100X60L35X80
  rect 0.55x0.8 smd: A(0.625,0) C(-0.625,0)
DO216-AA_STMITE
  rect 1.38x0.75 smd: A(1.555,0)
  rect 2.32x2.03 smd: C(-1.015,0)
DPAK4P228_972X240L120X77T520
  rrect 1.12x2.45 smd: 1(-2.3,-4.2) 3(2.3,-4.2)
  rrect 5.2x5.9 smd: 4(0,2.54)
DPAK4P254_1542X460L254X81T76-1
  rrect 1.6x3.5 smd: 1(-2.54,-6.7) 3(2.54,-6.7)
  rrect 12.2x9.75 smd: 4(0,3.575)
F_0603
  rrect 0.82x0.93 smd: 1(-0.755,0) 2(0.755,0)
HDRV1W64P0_1X1_254X254H834
  rect 1.59x1.59 hole 1.06: 1(0,0)
HDRV5W64P254_5X1_1270X254H838
  rect 1.59x1.59 hole 1.06: 1(0,0)
  round 1.59 hole 1.06: 2(2.54,0) 3(5.08,0) 4(7.62,0) 5(10.16,0)
JUMPER_P254_2PIN
  rect 1.59x1.59 hole 1.06: 1(0,0)
  round 1.59 hole 1.06: 2(2.54,0)
MICRO-USB_AB-MOLEX-0475900001
  rect 1.35x0.4 smd: 1(2.672,-1.3) 2(2.672,-0.65) 3(2.672,0) 4(2.673,0.649) 5(2.673,1.299)
  oval 1.25x1.05 hole 0.85x0.65: 6(3,2.225) 7(3,-2.225)
  oval 1.9x1.25 hole 1.5x0.8: 8(0,4.075) 9(0,-4.075)
MOR2_5_08MM
  round 2.8 hole 1.3: 1(0,2.54) 2(0,-2.54)
MOR6_WURTH-691231510006
  round 2.5 hole 1.4: 1(0,0) 2(5.08,0) 3(10.16,0) 4(-2.54,10.16) 5(2.54,10.16) 6(7.62,10.16)
MOR8_5_08MM
  round 2.8 hole 1.3: 1(0,2.54) 2(0,-2.54) 3(0,-7.62) 4(0,-12.7) 5(0,-17.78) 6(0,-22.86) 7(0,-27.94) 8(0,-33.02)
NCS1
  round 1.5 hole 1: 1(-8.665,0.905) 2(-6.125,0.905) 3(-3.585,0.905) 6(4.035,0.905) 7(6.575,0.905)
OSCCC250X200X90L67X77N
  rrect 0.96x0.86 smd: 1(-0.93,-0.73) 2(0.93,-0.73) 3(0.93,0.73) 4(-0.93,0.73)
POWER_FLAT_5X6
  rect 0.71x1.35 smd: 1(-1.905,-2.665) 2(-0.635,-2.665) 3(0.635,-2.665) 4(1.905,-2.665) 5(1.905,2.665) 6(0.635,2.665) 7(-0.635,2.665) 8(-1.905,2.665)
PUSH_BUTTON_TECONN_1437566-3
  rect 2.2x1.7 smd: 1(-4.6,2.3) 2(4.6,2.3)
QFN49P50_700X700X100L40X25T513N
  rrect 0.27x0.74 smd: 1(-2.75,-3.385) 2(-2.25,-3.385) 3(-1.75,-3.385) 4(-1.25,-3.385) 5(-0.75,-3.385) 6(-0.25,-3.385) 7(0.25,-3.385) 8(0.75,-3.385) 9(1.25,-3.385) 10(1.75,-3.385) 11(2.25,-3.385) 12(2.75,-3.385) 25(2.75,3.385) 26(2.25,3.385) 27(1.75,3.385) 28(1.25,3.385) 29(0.75,3.385) 30(0.25,3.385) 31(-0.25,3.385) 32(-0.75,3.385) 33(-1.25,3.385) 34(-1.75,3.385) 35(-2.25,3.385) 36(-2.75,3.385)
  rrect 0.74x0.27 smd: 13(3.385,-2.75) 14(3.385,-2.25) 15(3.385,-1.75) 16(3.385,-1.25) 17(3.385,-0.75) 18(3.385,-0.25) 19(3.385,0.25) 20(3.385,0.75) 21(3.385,1.25) 22(3.385,1.75) 23(3.385,2.25) 24(3.385,2.75) 37(-3.385,2.75) 38(-3.385,2.25) 39(-3.385,1.75) 40(-3.385,1.25) 41(-3.385,0.75) 42(-3.385,0.25) 43(-3.385,-0.25) 44(-3.385,-0.75) 45(-3.385,-1.25) 46(-3.385,-1.75) 47(-3.385,-2.25) 48(-3.385,-2.75)
  rrect 5.13x5.13 smd: 49(0,0)
QFP144P50_2200X2200X160L60X22N
  rrect 0.3x1.26 smd: 1(-8.75,-10.63) 2(-8.25,-10.63) 3(-7.75,-10.63) 4(-7.25,-10.63) 5(-6.75,-10.63) 6(-6.25,-10.63) 7(-5.75,-10.63) 8(-5.25,-10.63) 9(-4.75,-10.63) 10(-4.25,-10.63) 11(-3.75,-10.63) 12(-3.25,-10.63) 13(-2.75,-10.63) 14(-2.25,-10.63) 15(-1.75,-10.63) 16(-1.25,-10.63) 17(-0.75,-10.63) 18(-0.25,-10.63) 19(0.25,-10.63) 20(0.75,-10.63) 21(1.25,-10.63) 22(1.75,-10.63) 23(2.25,-10.63) 24(2.75,-10.63) 25(3.25,-10.63) 26(3.75,-10.63) 27(4.25,-10.63) 28(4.75,-10.63) 29(5.25,-10.63) 30(5.75,-10.63) 31(6.25,-10.63) 32(6.75,-10.63) 33(7.25,-10.63) 34(7.75,-10.63) 35(8.25,-10.63) 36(8.75,-10.63) 73(8.75,10.63) 74(8.25,10.63) 75(7.75,10.63) 76(7.25,10.63) 77(6.75,10.63) 78(6.25,10.63) 79(5.75,10.63) 80(5.25,10.63) 81(4.75,10.63) 82(4.25,10.63) 83(3.75,10.63) 84(3.25,10.63) 85(2.75,10.63) 86(2.25,10.63) 87(1.75,10.63) 88(1.25,10.63) 89(0.75,10.63) 90(0.25,10.63) 91(-0.25,10.63) 92(-0.75,10.63) 93(-1.25,10.63) 94(-1.75,10.63) 95(-2.25,10.63) 96(-2.75,10.63) 97(-3.25,10.63) 98(-3.75,10.63) 99(-4.25,10.63) 100(-4.75,10.63) 101(-5.25,10.63) 102(-5.75,10.63) 103(-6.25,10.63) 104(-6.75,10.63) 105(-7.25,10.63) 106(-7.75,10.63) 107(-8.25,10.63) 108(-8.75,10.63)
  rrect 1.26x0.3 smd: 37(10.63,-8.75) 38(10.63,-8.25) 39(10.63,-7.75) 40(10.63,-7.25) 41(10.63,-6.75) 42(10.63,-6.25) 43(10.63,-5.75) 44(10.63,-5.25) 45(10.63,-4.75) 46(10.63,-4.25) 47(10.63,-3.75) 48(10.63,-3.25) 49(10.63,-2.75) 50(10.63,-2.25) 51(10.63,-1.75) 52(10.63,-1.25) 53(10.63,-0.75) 54(10.63,-0.25) 55(10.63,0.25) 56(10.63,0.75) 57(10.63,1.25) 58(10.63,1.75) 59(10.63,2.25) 60(10.63,2.75) 61(10.63,3.25) 62(10.63,3.75) 63(10.63,4.25) 64(10.63,4.75) 65(10.63,5.25) 66(10.63,5.75) 67(10.63,6.25) 68(10.63,6.75) 69(10.63,7.25) 70(10.63,7.75) 71(10.63,8.25) 72(10.63,8.75) 109(-10.63,8.75) 110(-10.63,8.25) 111(-10.63,7.75) 112(-10.63,7.25) 113(-10.63,6.75) 114(-10.63,6.25) 115(-10.63,5.75) 116(-10.63,5.25) 117(-10.63,4.75) 118(-10.63,4.25) 119(-10.63,3.75) 120(-10.63,3.25) 121(-10.63,2.75) 122(-10.63,2.25) 123(-10.63,1.75) 124(-10.63,1.25) 125(-10.63,0.75) 126(-10.63,0.25) 127(-10.63,-0.25) 128(-10.63,-0.75) 129(-10.63,-1.25) 130(-10.63,-1.75) 131(-10.63,-2.25) 132(-10.63,-2.75) 133(-10.63,-3.25) 134(-10.63,-3.75) 135(-10.63,-4.25) 136(-10.63,-4.75) 137(-10.63,-5.25) 138(-10.63,-5.75) 139(-10.63,-6.25) 140(-10.63,-6.75) 141(-10.63,-7.25) 142(-10.63,-7.75) 143(-10.63,-8.25) 144(-10.63,-8.75)
R_0402
  rrect 0.58x0.58 smd: 1(-0.46,0) 2(0.46,0)
R_0603
  rrect 0.82x0.93 smd: 1(-0.755,0) 2(0.755,0)
R_0805
  rrect 0.92x1.38 smd: 1(-0.905,0) 2(0.905,0)
RHDRV1W64P0_1X1_305X254H851
  rect 1.59x1.59 hole 1.06: 1(0,0)
SHDRV10W40P127_5X2_1265X510H-1
  rect 1.12x1.12 hole 0.72: 1(0,0)
  round 1.12 hole 0.72: 2(0,1.27) 3(1.27,0) 4(1.27,1.27) 5(2.54,0) 6(2.54,1.27) 7(3.81,0) 8(3.81,1.27) 9(5.08,0) 10(5.08,1.27)
SODFL250X125X85L40X32N
  rrect 0.84x0.44 smd: A(1.14,0) C(-1.14,0)
SODFL517X257X110L97X145N
  rrect 1.46x1.67 smd: A(2.155,0) C(-2.155,0)
SOIC8P127_490X600X175L83X42N
  rrect 0.66x2.07 smd: 1(-1.905,-2.425) 2(-0.635,-2.425) 3(0.635,-2.425) 4(1.905,-2.425) 5(1.905,2.425) 6(0.635,2.425) 7(-0.635,2.425) 8(-1.905,2.425)
SOIC8P127_508X599X330L78X40
  rrect 0.64x1.91 smd: 1(-1.905,-2.79) 2(-0.635,-2.79) 3(0.635,-2.79) 4(1.905,-2.79) 5(1.905,2.79) 6(0.635,2.79) 7(-0.635,2.79) 8(-1.905,2.79)
SOIC8P127_599X610X350L51X41N
  rrect 0.64x1.6 smd: 1(-1.905,-2.73) 2(-0.635,-2.73) 3(0.635,-2.73) 4(1.905,-2.73) 5(1.905,2.73) 6(0.635,2.73) 7(-0.635,2.73) 8(-1.905,2.73)
SOIC16P127_990X600X175L83X41N
  rrect 0.66x2.07 smd: 1(-4.445,-2.582) 2(-3.175,-2.582) 3(-1.905,-2.582) 4(-0.635,-2.582) 5(0.635,-2.582) 6(1.905,-2.582) 7(3.175,-2.582) 8(4.445,-2.582) 9(4.445,2.582) 10(3.175,2.582) 11(1.905,2.582) 12(0.635,2.582) 13(-0.635,2.582) 14(-1.905,2.582) 15(-3.175,2.582) 16(-4.445,2.582)
SON6P50_170X150X55L40X24
  rrect 0.25x0.6 smd: 1(-0.5,-0.65) 2(0,-0.65) 3(0.5,-0.65) 4(0.5,0.65) 5(0,0.65) 6(-0.5,0.65)
SON9P65_300X300X100L40X30T310X190
  rrect 0.32x0.64 smd: 1(-0.975,-1.47) 2(-0.325,-1.47) 3(0.325,-1.47) 4(0.975,-1.47) 5(0.975,1.47) 6(0.325,1.47) 7(-0.325,1.47) 8(-0.975,1.47)
  rrect 3.1x1.9 smd: 9(0,0)
SON17P40_330X135X55L25X20T280X40
  rrect 0.2x0.45 smd: 1(-1.4,-0.65) 2(-1,-0.65) 3(-0.6,-0.65) 4(-0.2,-0.65) 5(0.2,-0.65) 6(0.6,-0.65) 7(1,-0.65) 8(1.4,-0.65) 9(1.4,0.65) 10(1,0.65) 11(0.6,0.65) 12(0.2,0.65) 13(-0.2,0.65) 14(-0.6,0.65) 15(-1,0.65) 16(-1.4,0.65)
  rect 2.8x0.4 smd: 17(0,0)
SOP21P65_650X640X120L60X24T420X300N
  rect 0.39x1.36 smd: 1(-2.925,-2.83)
  rrect 0.39x1.36 smd: 2(-2.275,-2.83) 3(-1.625,-2.83) 4(-0.975,-2.83) 5(-0.325,-2.83) 6(0.325,-2.83) 7(0.975,-2.83) 8(1.625,-2.83) 9(2.275,-2.83) 10(2.925,-2.83) 11(2.925,2.83) 12(2.275,2.83) 13(1.625,2.83) 14(0.975,2.83) 15(0.325,2.83) 16(-0.325,2.83) 17(-0.975,2.83) 18(-1.625,2.83) 19(-2.275,2.83) 20(-2.925,2.83)
  rrect 4.2x3 smd: 21(0,0)
SOP86P50_2222X1176X120L50X22N
  rrect 0.3x1.14 smd: 1(-10.5,-5.57) 2(-10,-5.57) 3(-9.5,-5.57) 4(-9,-5.57) 5(-8.5,-5.57) 6(-8,-5.57) 7(-7.5,-5.57) 8(-7,-5.57) 9(-6.5,-5.57) 10(-6,-5.57) 11(-5.5,-5.57) 12(-5,-5.57) 13(-4.5,-5.57) 14(-4,-5.57) 15(-3.5,-5.57) 16(-3,-5.57) 17(-2.5,-5.57) 18(-2,-5.57) 19(-1.5,-5.57) 20(-1,-5.57) 21(-0.5,-5.57) 22(0,-5.57) 23(0.5,-5.57) 24(1,-5.57) 25(1.5,-5.57) 26(2,-5.57) 27(2.5,-5.57) 28(3,-5.57) 29(3.5,-5.57) 30(4,-5.57) 31(4.5,-5.57) 32(5,-5.57) 33(5.5,-5.57) 34(6,-5.57) 35(6.5,-5.57) 36(7,-5.57) 37(7.5,-5.57) 38(8,-5.57) 39(8.5,-5.57) 40(9,-5.57) 41(9.5,-5.57) 42(10,-5.57) 43(10.5,-5.57) 44(10.5,5.57) 45(10,5.57) 46(9.5,5.57) 47(9,5.57) 48(8.5,5.57) 49(8,5.57) 50(7.5,5.57) 51(7,5.57) 52(6.5,5.57) 53(6,5.57) 54(5.5,5.57) 55(5,5.57) 56(4.5,5.57) 57(4,5.57) 58(3.5,5.57) 59(3,5.57) 60(2.5,5.57) 61(2,5.57) 62(1.5,5.57) 63(1,5.57) 64(0.5,5.57) 65(0,5.57) 66(-0.5,5.57) 67(-1,5.57) 68(-1.5,5.57) 69(-2,5.57) 70(-2.5,5.57) 71(-3,5.57) 72(-3.5,5.57) 73(-4,5.57) 74(-4.5,5.57) 75(-5,5.57) 76(-5.5,5.57) 77(-6,5.57) 78(-6.5,5.57) 79(-7,5.57) 80(-7.5,5.57) 81(-8,5.57) 82(-8.5,5.57) 83(-9,5.57) 84(-9.5,5.57) 85(-10,5.57) 86(-10.5,5.57)
SOT23-3P97_255X140L40X40N
  rrect 0.64x1.38 smd: 1(-0.97,-1.165) 2(0.97,-1.165) 3(0,1.165)
SOT23-5P95_280X145L45X40N
  rrect 0.61x1.16 smd: 1(-0.95,-1.23) 2(0,-1.23) 3(0.95,-1.23) 4(0.95,1.23) 5(-0.95,1.23)
ST_TFQFPN32
  rect 0.35x0.7 smd: 1(-4.85,-4.3) 20(-4.85,4.3)
  rect 0.3x0.7 smd: 2(3.15,-4.3) 3(3.55,-4.3) 18(3.55,4.3) 19(3.15,4.3)
  rect 0.7x0.3 smd: 4(5.3,-3.35) 5(5.3,-2.95) 6(5.3,-2.3) 7(5.3,-1.9) 8(5.3,-1.25) 9(5.3,-0.85) 10(5.3,-0.2) 11(5.3,0.2) 12(5.3,0.85) 13(5.3,1.25) 14(5.3,1.9) 15(5.3,2.3) 16(5.3,2.95) 17(5.3,3.35)
  rect 0.7x0.35 smd: 21(-5.3,3.575) 22(-5.3,2.925) 23(-5.3,2.275) 24(-5.3,1.625) 25(-5.3,0.975) 26(-5.3,0.325) 27(-5.3,-0.325) 28(-5.3,-0.975) 29(-5.3,-1.625) 30(-5.3,-2.275) 31(-5.3,-2.925) 32(-5.3,-3.575)
  rect 1.33x1.2 smd: TAB1(-0.815,-2.8) TAB3(-0.815,2.8)
  rect 1.6x3.4 smd: TAB2(-0.95,0)
  rect 4.5x6.9 smd: TAB4(2.5,0)
STRIP1X3_254
  rect 1.57x1.57 hole 1: 1(0,0)
  round 1.57 hole 1: 2(0,2.54) 3(0,5.08)
TAN_2917
  rrect 2.15x4.52 smd: 1(-3.185,0) 2(3.185,0)
unnamed#2
  round 3.5 hole 3.5 unplated: (0,-0.1)
XTALDFN2_320X150X90L75X130
  rect 1x1.8 smd: 1(-1.25,0) 2(1.25,0)

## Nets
3V3: C96.1 L5.1 L6.1 R150.1 U26.5(OUT)
5V: D45.3 L1.1 R83.1 U21.5 U24.6 U29.1
5V_FIELD: C31.2 C35.2 C40.1 C43.1 C94.2 C95.1 D42.C(CATHODE) R49.2 R51.2 R52.2 R54.2 R55.2 R58.2 R59.2 R62.2 U7.8(VDD) U9.8(VDD) U23.3(OUT)
24V: C84.1 F1.1 J19.2
24V_FIELD: C34.2 C36.2 C37.1 C45.1 C46.2 C85.1 C88.1 C89.1 C93.1 C130.1 J6.3 J6.6 J10.1 J26.2 L4.2 R13.1 R15.1 R27.1 R28.1 R29.1 R30.1 R142.2 U8.13 U13.TAB4 U23.1 U24.2 U29.7
GND_CLT1: C1.2 C2.2 C3.2 C4.2 C5.2 C6.1 C14.2 C129.2 J2.1 J4.1 R5.2 R194.1 TP4.1 TP14.1 U1.43 U2.9
GND_EARTH: C84.2 C91.1 J20.1
GND_EXT: J25.3 J25.4 R177.1 U28.4(K2)
GND_FIELD: C7.1 C8.1 C9.1 C10.1 C11.2 C12.1 C13.1 C17.1 C18.1 C34.1 C36.1 C37.2 C45.2 C46.1 C47.1 C48.1 C49.1 C51.1 C52.1 C56.1 C58.1 C59.1 C85.2 C86.2 C87.2 C88.2 C89.2 C91.2 C93.2 C94.1 C130.2 D1.C D2.C D3.C D4.C D5.C D6.C D7.C D8.C D24.C D25.C D26.C D28.C D30.C D31.C D32.C D33.C D39.2(I/O2) D40.C D42.A J7.1 J7.4 J8.2 J9.2 J19.1 J26.1 R16.2 R40.2 R45.2 R145.1 R194.2 R195.2 TP13.1 TP17.1 U1.3 U1.5 U1.6 U1.7 U1.8 U1.9 U1.10 U1.11 U1.12 U1.15 U1.20 U1.25 U1.26 U1.27 U1.28 U1.29 U1.30 U1.31 U1.32 U1.33 U1.49 U8.1 U8.2 U8.19 U8.20 U13.3 U13.TAB1 U13.TAB2 U13.TAB3 U23.4 U24.1 U29.6
GND_LCD: C62.1 C63.2 C64.1 C65.2 C66.1 C128.1 L3.2 Q1.2(E) R85.1 R86.1 TP18.1 U14.3 U14.9
GND_LOGIC: BT1.3(-) C15.2 C16.2 C22.2 C24.1 C29.1 C30.2 C41.2 C42.2 C44.2 C50.1 C53.1 C54.1 C55.1 C57.1 C60.2 C61.2 C67.1 C68.2 C69.2 C70.2 C71.2 C72.2 C73.2 C74.2 C75.2 C76.2 C77.2 C78.2 C79.2 C80.2 C81.2 C82.1 C83.2 C92.2 C96.2 C97.2 C98.2 C99.2 C100.1 C101.1 C102.2 C103.2 C104.2 C105.2 C106.2 C107.1 C108.1 C109.1 C110.2 C111.2 C112.1 C113.1 C114.1 C115.1 C116.1 C117.1 C118.1 C119.1 C120.1 C121.1 C122.1 C123.1 C124.2 C125.2 C126.2 C127.1 D27.A D43.A D44.A D48.C D49.A J17.8 J17.20 J17.22 J18.9 J18.20 J18.32 J23.3 J23.5 J23.9 L3.1 Q2.2(E) Q3.2(E) Q5.2(E) R31.2 R34.2 R39.2 R42.2 R87.2 R88.1 R89.2 R90.1 R91.2 R92.1 R93.2 R100.1 R101.2 R102.2 R103.2 R107.1 R110.1 R111.2 R112.1 R114.1 R116.2 R117.2 R119.1 R120.2 R124.1 R125.2 R127.1 R128.2 R132.1 R133.2 R141.2 R147.1 R151.2 R171.2 R172.1 R176.1 R181.2 R193.2 SW1.1 SW2.2 TP3.1 TP12.1 TP15.1 U2.8 U3.5 U6.5 U10.5 U11.5 U12.5 U13.1 U15.3 U15.29 U15.35 U15.36 U16.17 U17.17 U18.17 U19.6 U19.12 U19.32 U19.38 U19.44 U19.46 U19.52 U19.58 U19.72 U19.78 U19.84 U19.86(VSS_3) U20.4 U21.2 U22.1 U22.9 U24.7 U25.3 U26.2 U27.16 U27.31 U27.38 U27.51 U27.61 U27.83 U27.94 U27.107 U27.120 U27.130 U29.2 Y2.2
GND_SIGNAL: C31.1 C32.1 C33.1 C35.1 C38.1 C39.1 C40.2 C43.2 C95.2 R44.2 R47.2 R195.1 U7.5 U8.8 U8.21 U9.5
VDD: C15.1 C16.1 C22.1 C24.2 C29.2 C30.1 C41.1 C42.1 C44.1 C60.1 C61.1 C67.2 C68.1 C69.1 C70.1 C71.1 C72.1 C73.1 C74.1 C75.1 C76.1 C77.1 C78.1 C79.1 C80.1 C81.1 C82.2 C83.1 C97.1 C99.1 C106.1 C107.2 C108.2 C109.2 C110.1 C113.2 C114.2 C115.2 C116.2 C117.2 C118.2 C119.2 C120.2 C121.2 C122.2 C123.2 C126.1 D29.A D34.A J17.5 J17.16 J17.33 J17.34 J18.7 J23.1 L5.2 R65.2 R94.1 R137.1 R143.2 R146.1 R149.1 R167.1 R169.1 R170.1 R179.1 R182.2 R183.1 R185.2 U2.1 U3.8(VDD) U6.8(VDD) U10.8(VDD) U11.8(VDD) U12.8(VDD) U13.20(VDD) U15.4 U19.1 U19.3 U19.9 U19.15 U19.29 U19.35 U19.41 U19.43 U19.49 U19.55 U19.75 U19.81 U20.8(VCC) U27.17 U27.30 U27.39 U27.52 U27.62 U27.72 U27.84 U27.95 U27.108 U27.121 U27.131 U27.144 U28.6 Y2.4
VDD_CLT: C5.1 C6.2 C14.1 C129.1 J2.3 J4.3 R6.2 U2.16(VDD2)
VDD_EXT: J25.1 U28.8
BOOT0: R170.2 R171.1
BOOTO: U27.138
CLT_CS1: R1.2 U2.13
CLT_IN1: C7.2 R7.2 U1.16
CLT_IN2: C8.2 R9.2 U1.17
CLT_IN3: C9.2 R11.2 U1.18
CLT_IN4: C10.2 R12.2 U1.19
CLT_IN5: C12.2 R14.2 U1.21
CLT_IN6: C13.2 R17.2 U1.22
CLT_IN7: C17.2 R19.2 U1.23
CLT_IN8: C18.2 R22.2 U1.24
CLT_MISO: C1.1 R4.2 TP1.1 U2.10
CLT_MOSI: R3.2 U2.15
CLT_SCK: R2.2 U2.14
DI_FLT_Q1_1: U11.7 U27.5
DI_FLT_Q1_2: U11.6 U27.7
DI_FLT_Q1_3: U10.7 U27.118
DI_FLT_Q1_4: U10.6 U27.135
DI_FLT_Q1_FLT: U12.7 U27.100
DI_FLT_Q1_OL: U12.6 U27.99
DI_I1_1: U3.7 U27.1
DI_I1_2: U3.6 U27.2
DI_I1_3: U6.7 U27.3
DI_I1_4: U6.6 U27.4
DI_Q0_FLT: R78.2 U27.129
DI_Q0_PGOOD: R82.1 U27.128
DO_LCD_BL_CTRL: R84.1 U27.34
DO_Q0_EN: R64.2 U27.45
DO_Q1_1: R32.2 U27.76
DO_Q1_2: R36.2 U27.80
DO_Q1_3: R46.2 U27.98
DO_Q1_4: R48.2 U27.113
ENCQ: R115.1 R118.1 R158.2
ENL+: R98.2 R139.1 R159.2 R188.1
FLT: D21.C R61.2 U8.10
FMC_ADD.A0: U19.25 U27.10
FMC_ADD.A1: U19.26 U27.11
FMC_ADD.A2: U19.27 U27.12
FMC_ADD.A3: U19.60 U27.13
FMC_ADD.A4: U19.61 U27.14
FMC_ADD.A5: U19.62 U27.15
FMC_ADD.A6: U19.63 U27.50
FMC_ADD.A7: U19.64 U27.53
FMC_ADD.A8: U19.65 U27.54
FMC_ADD.A9: U19.66 U27.55
FMC_ADD.A10: U19.24 U27.56
FMC_ADD.A11: U19.21 U27.57
FMC_ADD.BA_0: U19.22 U27.89
FMC_ADD.BA_1: U19.23 U27.90
FMC_CTRL.NBL0: U19.16 U27.141
FMC_CTRL.NBL1: U19.71 U27.142
FMC_CTRL.SDCKE0: U19.67 U27.29
FMC_CTRL.SDCLK: U19.68 U27.93
FMC_CTRL.SDNCAS: U19.18 U27.132
FMC_CTRL.SDNE0: U19.20 U27.44
FMC_CTRL.SDNRAS: U19.19 U27.49
FMC_CTRL.SDNWE: U19.17 U27.43
FMC_DATA.D0: U19.2 U27.85
FMC_DATA.D1: U19.4 U27.86
FMC_DATA.D2: U19.5 U27.114
FMC_DATA.D3: U19.7 U27.115
FMC_DATA.D4: U19.8 U27.58
FMC_DATA.D5: U19.10 U27.59
FMC_DATA.D6: U19.11 U27.60
FMC_DATA.D7: U19.13 U27.63
FMC_DATA.D8: U19.74 U27.64
FMC_DATA.D9: U19.76 U27.65
FMC_DATA.D10: U19.77 U27.66
FMC_DATA.D11: U19.79 U27.67
FMC_DATA.D12: U19.80 U27.68
FMC_DATA.D13: U19.82 U27.77
FMC_DATA.D14: U19.83 U27.78(PD9)
FMC_DATA.D15: U19.85 U27.79
I0.0: J1.8 R7.1
I0.1: J1.7 R9.1
I0.2: J1.6 R11.1
I0.3: J1.5 R12.1
I0.4: J1.4 R14.1
I0.5: J1.3 R17.1
I0.6: J1.2 R19.1
I0.7: J1.1 R22.1
I1.0H: C20.1 J6.2 U4.6 U4.7
I1.0L: C20.2 J6.5 U4.8
I1.1H: C23.1 J6.1 U4.2 U4.3
I1.1L: C23.2 J6.4 U4.4
I1.2H: C26.1 J7.3 U5.6 U5.7
I1.2L: C26.2 J7.6 U5.8
I1.3H: C28.1 J7.2 U5.2 U5.3
I1.3L: C28.2 J7.5 U5.4
I2C1_SCL: R105.2 U27.136
I2C1_SDA: R108.2 U27.137
IN1_FLT: C33.2 D17.A R33.1 R57.2 U8.4
IN2_FLT: C32.2 D18.A R35.1 R56.2 U8.5
IN3_FLT: C38.2 D19.A R41.1 R53.2 TP8.1 U8.6
IN4_FLT: C39.2 D20.A R43.1 R50.2 U8.7
IO-RST: R122.1 R123.1 R164.2
IRQ: R99.2 R134.1 R162.2 R187.1
L+ON: R131.1 R135.1 R140.1 R165.2
LCD_BLUE2: R193.1 U15.23 U17.13
LCD_BLUE3: U15.24 U17.14
LCD_BLUE4: U15.25 U17.15
LCD_BLUE5: U15.26 U17.16
LCD_BLUE6: U15.27 U16.9(OUT8)
LCD_BLUE7: U15.28 U16.10
LCD_BLUE.B2: U17.4
LCD_BLUE.B3: U17.3 U27.126
LCD_BLUE.B4: U17.2 U27.127
LCD_BLUE.B5: U17.1 U27.37
LCD_BLUE.B6: U16.8 U27.139
LCD_BLUE.B7: U16.7 U27.140
LCD_CLK: U16.6 U27.92
LCD_CLK2: U15.30 U16.11
LCD_DE: U16.2 U27.22
LCD_DE2: U15.34 U16.15
LCD_DISP: U16.5 U27.119
LCD_DISP2: U15.31 U16.12
LCD_GREEN2: U15.15 U18.15
LCD_GREEN3: U15.16 U18.16
LCD_GREEN4: U15.17 U17.9(OUT8)
LCD_GREEN5: U15.18 U17.10
LCD_GREEN6: U15.19 U17.11
LCD_GREEN7: U15.20 U17.12
LCD_GREEN.G2: U18.2 U27.42
LCD_GREEN.G3: U18.1 U27.125
LCD_GREEN.G4: U17.8 U27.69
LCD_GREEN.G5: U17.7 U27.70
LCD_GREEN.G6: U17.6 U27.97
LCD_GREEN.G7: U17.5 U27.117
LCD_HSYNC: U16.4 U27.96
LCD_HSYNC2: U15.32 U16.13
LCD_INT: U15.38 U27.124
LCD_RED2: R93.1 U15.7 U18.9(OUT8)
LCD_RED3: U15.8 U18.10
LCD_RED4: U15.9 U18.11
LCD_RED5: U15.10 U18.12
LCD_RED6: U15.11 U18.13
LCD_RED7: U15.12 U18.14
LCD_RED.R2: R152.2 U18.8
LCD_RED.R3: U18.7 U27.46
LCD_RED.R4: U18.6 U27.41
LCD_RED.R5: U18.5 U27.26
LCD_RED.R6: U18.4 U27.47
LCD_RED.R7: U18.3 U27.91
LCD_RST: C127.2 D49.C(CATHODE) J23.10 R182.1 R186.1 SW2.1 U15.37 U27.25
LCD_SCL: R167.2 U15.39 U27.81
LCD_SDA: R169.2 U15.40 U27.82
LCD_VSYNC: U16.3 U27.40
LCD_VSYNC2: U15.33 U16.14
OL: D22.C R60.2 U8.9
OL-OFF: R95.2 R97.1 U27.75
OUTN1: C19.2 R23.1 U3.2 U4.5 U4.TAB1
OUTN2: C21.2 R24.1 U3.3 U4.13 U4.TAB2
OUTN3: C25.2 R25.1 U5.5 U5.TAB1 U6.2
OUTN4: C27.2 R26.1 U5.13 U5.TAB2 U6.3
OUTP1: D9.A TP5.1 U4.11
OUTP2: D10.A U4.16
OUTP3: D11.A U5.11
OUTP4: D12.A TP6.1 U5.16
PA1: R130.2 R153.2 R189.2
PC10: J22.2 U27.111
PC11: J24.2 U27.112
PD6/B2: R20.1 U27.122
PDR_ON: R179.2 R181.1 U27.143
PGOOD: R81.2 R82.2 U13.25
Q0.0: C59.2 J14.1 R80.1 U13.4 U13.5
Q0.1: C58.2 J14.2 R79.1 U13.6 U13.7
Q0.2: C56.2 J14.3 R77.1 U13.8 U13.9
Q0.3: C52.2 J14.4 R73.1 U13.10 U13.11
Q0.4: C51.2 J14.5 R70.1 U13.12 U13.13
Q0.5: C49.2 J14.6 R67.1 U13.14 U13.15
